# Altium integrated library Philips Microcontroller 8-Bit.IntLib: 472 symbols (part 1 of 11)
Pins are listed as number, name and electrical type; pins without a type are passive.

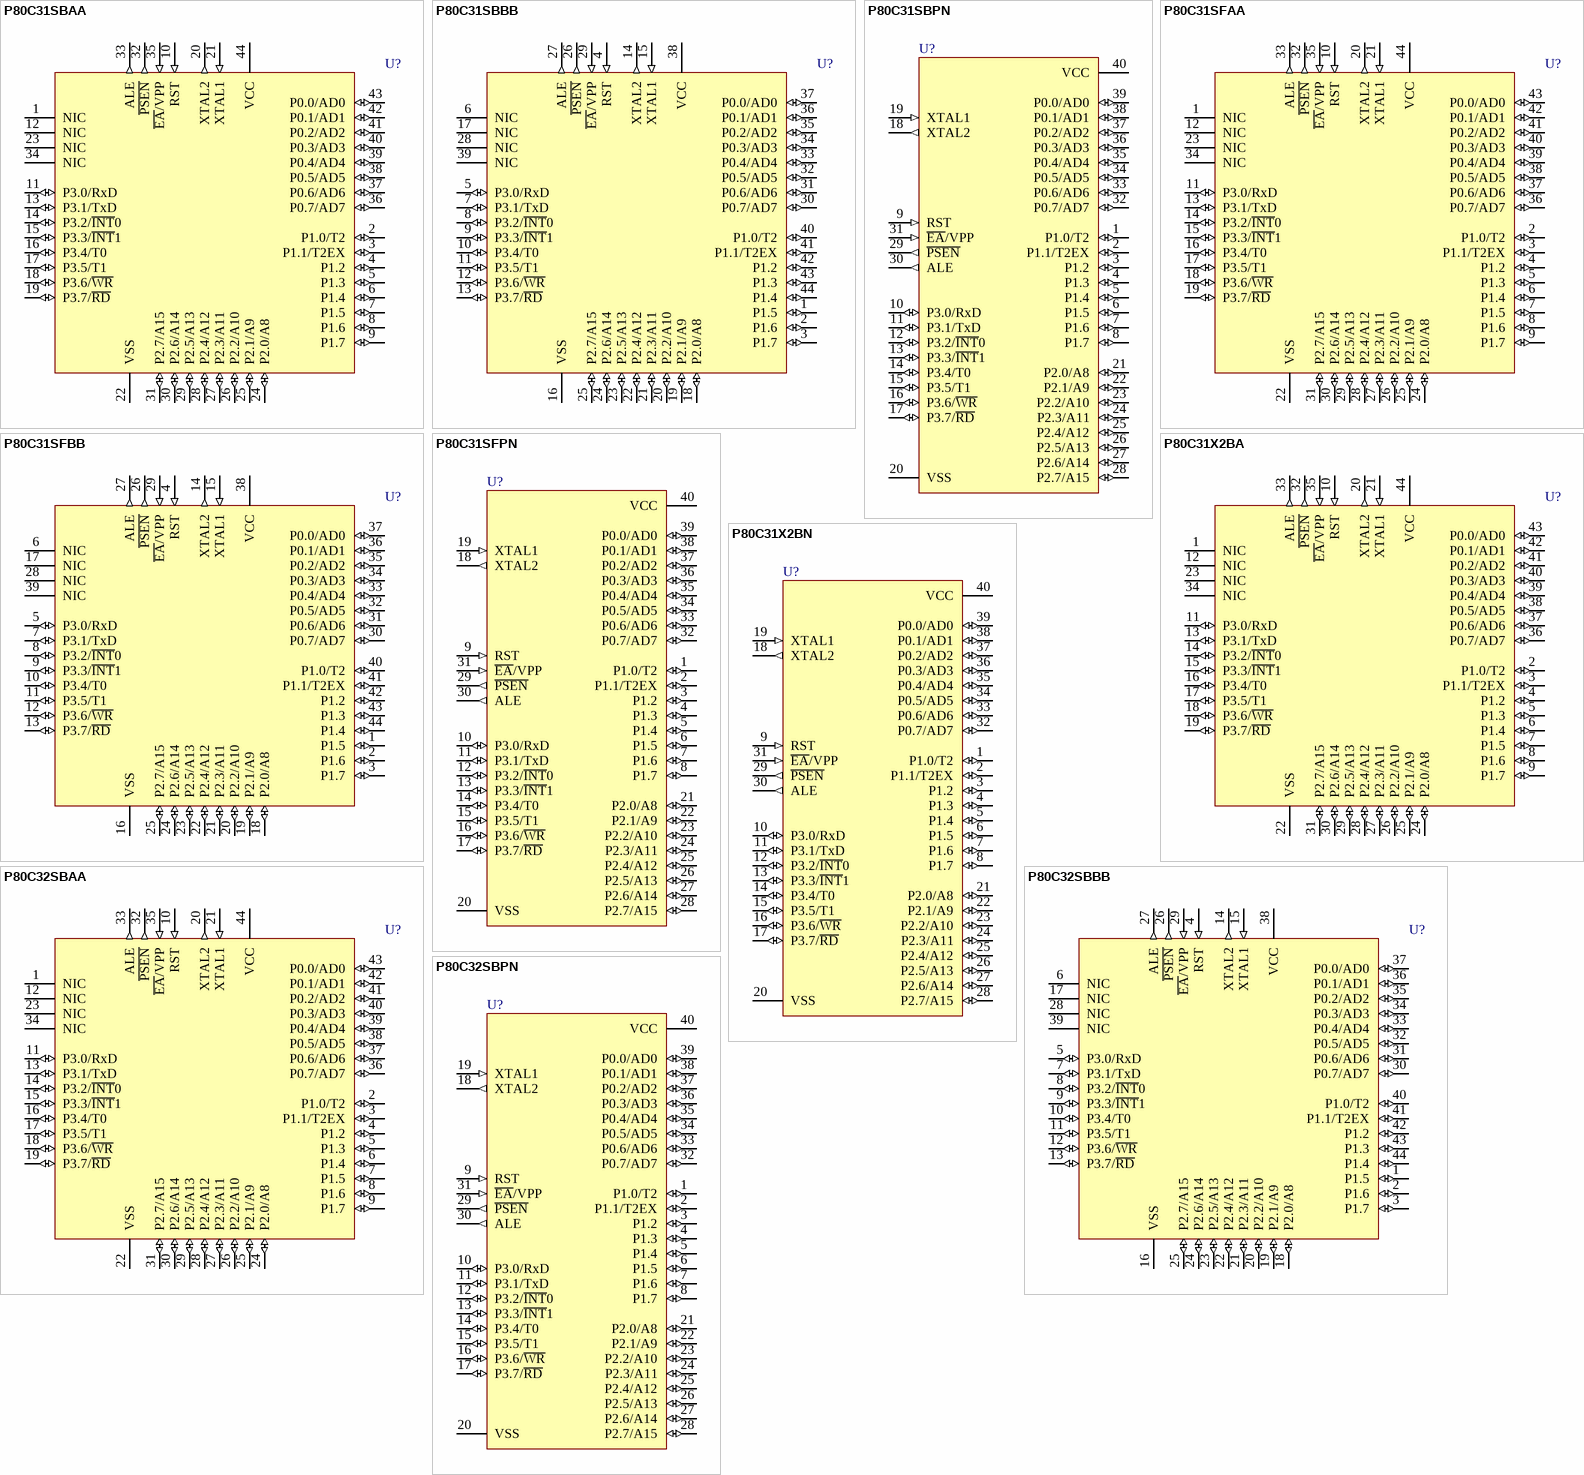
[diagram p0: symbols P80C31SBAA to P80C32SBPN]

## P80C31SBAA
designator U?
80C51 8-Bit Microcontroller Family: 128 B RAM, ROMless, 2.7 V-5.5 V, Low Power, High Speed
footprint SOT187-2_N (Leaded Chip Carrier, 44-Leads, Body 16.6x16.6mm, Pitch 1.27mm, IPC Medium Density)
footprint SOT187-2_L (Leaded Chip Carrier, 44-Leads, Body 16.6x16.6mm, Pitch 1.27mm, IPC High Density)
footprint SOT187-2_M (Leaded Chip Carrier, 44-Leads, Body 16.6x16.6mm, Pitch 1.27mm, IPC Low Density)
pins: 1 NIC, 2 P1.0/T2 (io), 3 P1.1/T2EX (io), 4 P1.2 (io), 5 P1.3 (io), 6 P1.4 (io), 7 P1.5 (io), 8 P1.6 (io), 9 P1.7 (io), 10 RST (in), 11 P3.0/RxD (io), 12 NIC, 13 P3.1/TxD (io), 14 P3.2/~{INT}0 (io), 15 P3.3/~{INT}1 (io), 16 P3.4/T0 (io), 17 P3.5/T1 (io), 18 P3.6/~{WR} (io), 19 P3.7/~{RD} (io), 20 XTAL2 (out), 21 XTAL1 (in), 22 VSS (power), 23 NIC, 24 P2.0/A8 (io), 25 P2.1/A9 (io), 26 P2.2/A10 (io), 27 P2.3/A11 (io), 28 P2.4/A12 (io), 29 P2.5/A13 (io), 30 P2.6/A14 (io), 31 P2.7/A15 (io), 32 ~{PSEN} (out), 33 ALE (out), 34 NIC, 35 ~{EA}/VPP (in), 36 P0.7/AD7 (io), 37 P0.6/AD6 (io), 38 P0.5/AD5 (io), 39 P0.4/AD4 (io), 40 P0.3/AD3 (io), 41 P0.2/AD2 (io), 42 P0.1/AD1 (io), 43 P0.0/AD0 (io), 44 VCC (power)

## P80C31SBBB
designator U?
80C51 8-Bit Microcontroller Family: 128 B RAM, ROMless, 2.7 V-5.5 V, Low Power, High Speed
footprint SOT307-2_N (QFP, 44-Leads, Body 10x10mm, Pitch 0.8mm, IPC Medium Density)
footprint SOT307-2_L (QFP, 44-Leads, Body 10x10mm, Pitch 0.8mm, IPC High Density)
footprint SOT307-2_M (QFP, 44-Leads, Body 10x10mm, Pitch 0.8mm, IPC Low Density)
pins: 1 P1.5 (io), 2 P1.6 (io), 3 P1.7 (io), 4 RST (in), 5 P3.0/RxD (io), 6 NIC, 7 P3.1/TxD (io), 8 P3.2/~{INT}0 (io), 9 P3.3/~{INT}1 (io), 10 P3.4/T0 (io), 11 P3.5/T1 (io), 12 P3.6/~{WR} (io), 13 P3.7/~{RD} (io), 14 XTAL2 (out), 15 XTAL1 (in), 16 VSS (power), 17 NIC, 18 P2.0/A8 (io), 19 P2.1/A9 (io), 20 P2.2/A10 (io), 21 P2.3/A11 (io), 22 P2.4/A12 (io), 23 P2.5/A13 (io), 24 P2.6/A14 (io), 25 P2.7/A15 (io), 26 ~{PSEN} (out), 27 ALE (out), 28 NIC, 29 ~{EA}/VPP (in), 30 P0.7/AD7 (io), 31 P0.6/AD6 (io), 32 P0.5/AD5 (io), 33 P0.4/AD4 (io), 34 P0.3/AD3 (io), 35 P0.2/AD2 (io), 36 P0.1/AD1 (io), 37 P0.0/AD0 (io), 38 VCC (power), 39 NIC, 40 P1.0/T2 (io), 41 P1.1/T2EX (io), 42 P1.2 (io), 43 P1.3 (io), 44 P1.4 (io)

## P80C31SBPN
designator U?
80C51 8-Bit Microcontroller Family: 128 B RAM, ROMless, 2.7 V-5.5 V, Low Power, High Speed
footprint SOT129-1 (DIP, Plastic; 40 Leads; Row Spacing 15.24 mm; Pitch 2.54 mm)
pins: 1 P1.0/T2 (io), 2 P1.1/T2EX (io), 3 P1.2 (io), 4 P1.3 (io), 5 P1.4 (io), 6 P1.5 (io), 7 P1.6 (io), 8 P1.7 (io), 9 RST (in), 10 P3.0/RxD (io), 11 P3.1/TxD (io), 12 P3.2/~{INT}0 (io), 13 P3.3/~{INT}1 (io), 14 P3.4/T0 (io), 15 P3.5/T1 (io), 16 P3.6/~{WR} (io), 17 P3.7/~{RD} (io), 18 XTAL2 (out), 19 XTAL1 (in), 20 VSS (power), 21 P2.0/A8 (io), 22 P2.1/A9 (io), 23 P2.2/A10 (io), 24 P2.3/A11 (io), 25 P2.4/A12 (io), 26 P2.5/A13 (io), 27 P2.6/A14 (io), 28 P2.7/A15 (io), 29 ~{PSEN} (out), 30 ALE (out), 31 ~{EA}/VPP (in), 32 P0.7/AD7 (io), 33 P0.6/AD6 (io), 34 P0.5/AD5 (io), 35 P0.4/AD4 (io), 36 P0.3/AD3 (io), 37 P0.2/AD2 (io), 38 P0.1/AD1 (io), 39 P0.0/AD0 (io), 40 VCC (power)

## P80C31SFAA
designator U?
80C51 8-Bit Microcontroller Family: 128 B RAM, ROMless, 2.7 V-5.5 V, Low Power, High Speed
footprint SOT187-2_N (Leaded Chip Carrier, 44-Leads, Body 16.6x16.6mm, Pitch 1.27mm, IPC Medium Density)
footprint SOT187-2_L (Leaded Chip Carrier, 44-Leads, Body 16.6x16.6mm, Pitch 1.27mm, IPC High Density)
footprint SOT187-2_M (Leaded Chip Carrier, 44-Leads, Body 16.6x16.6mm, Pitch 1.27mm, IPC Low Density)
pins: 1 NIC, 2 P1.0/T2 (io), 3 P1.1/T2EX (io), 4 P1.2 (io), 5 P1.3 (io), 6 P1.4 (io), 7 P1.5 (io), 8 P1.6 (io), 9 P1.7 (io), 10 RST (in), 11 P3.0/RxD (io), 12 NIC, 13 P3.1/TxD (io), 14 P3.2/~{INT}0 (io), 15 P3.3/~{INT}1 (io), 16 P3.4/T0 (io), 17 P3.5/T1 (io), 18 P3.6/~{WR} (io), 19 P3.7/~{RD} (io), 20 XTAL2 (out), 21 XTAL1 (in), 22 VSS (power), 23 NIC, 24 P2.0/A8 (io), 25 P2.1/A9 (io), 26 P2.2/A10 (io), 27 P2.3/A11 (io), 28 P2.4/A12 (io), 29 P2.5/A13 (io), 30 P2.6/A14 (io), 31 P2.7/A15 (io), 32 ~{PSEN} (out), 33 ALE (out), 34 NIC, 35 ~{EA}/VPP (in), 36 P0.7/AD7 (io), 37 P0.6/AD6 (io), 38 P0.5/AD5 (io), 39 P0.4/AD4 (io), 40 P0.3/AD3 (io), 41 P0.2/AD2 (io), 42 P0.1/AD1 (io), 43 P0.0/AD0 (io), 44 VCC (power)

## P80C31SFBB
designator U?
80C51 8-Bit Microcontroller Family: 128 B RAM, ROMless, 2.7 V-5.5 V, Low Power, High Speed
footprint SOT307-2_N (QFP, 44-Leads, Body 10x10mm, Pitch 0.8mm, IPC Medium Density)
footprint SOT307-2_L (QFP, 44-Leads, Body 10x10mm, Pitch 0.8mm, IPC High Density)
footprint SOT307-2_M (QFP, 44-Leads, Body 10x10mm, Pitch 0.8mm, IPC Low Density)
pins: 1 P1.5 (io), 2 P1.6 (io), 3 P1.7 (io), 4 RST (in), 5 P3.0/RxD (io), 6 NIC, 7 P3.1/TxD (io), 8 P3.2/~{INT}0 (io), 9 P3.3/~{INT}1 (io), 10 P3.4/T0 (io), 11 P3.5/T1 (io), 12 P3.6/~{WR} (io), 13 P3.7/~{RD} (io), 14 XTAL2 (out), 15 XTAL1 (in), 16 VSS (power), 17 NIC, 18 P2.0/A8 (io), 19 P2.1/A9 (io), 20 P2.2/A10 (io), 21 P2.3/A11 (io), 22 P2.4/A12 (io), 23 P2.5/A13 (io), 24 P2.6/A14 (io), 25 P2.7/A15 (io), 26 ~{PSEN} (out), 27 ALE (out), 28 NIC, 29 ~{EA}/VPP (in), 30 P0.7/AD7 (io), 31 P0.6/AD6 (io), 32 P0.5/AD5 (io), 33 P0.4/AD4 (io), 34 P0.3/AD3 (io), 35 P0.2/AD2 (io), 36 P0.1/AD1 (io), 37 P0.0/AD0 (io), 38 VCC (power), 39 NIC, 40 P1.0/T2 (io), 41 P1.1/T2EX (io), 42 P1.2 (io), 43 P1.3 (io), 44 P1.4 (io)

## P80C31SFPN
designator U?
80C51 8-Bit Microcontroller Family: 128 B RAM, ROMless, 2.7 V-5.5 V, Low Power, High Speed
footprint SOT129-1 (DIP, Plastic; 40 Leads; Row Spacing 15.24 mm; Pitch 2.54 mm)
pins: 1 P1.0/T2 (io), 2 P1.1/T2EX (io), 3 P1.2 (io), 4 P1.3 (io), 5 P1.4 (io), 6 P1.5 (io), 7 P1.6 (io), 8 P1.7 (io), 9 RST (in), 10 P3.0/RxD (io), 11 P3.1/TxD (io), 12 P3.2/~{INT}0 (io), 13 P3.3/~{INT}1 (io), 14 P3.4/T0 (io), 15 P3.5/T1 (io), 16 P3.6/~{WR} (io), 17 P3.7/~{RD} (io), 18 XTAL2 (out), 19 XTAL1 (in), 20 VSS (power), 21 P2.0/A8 (io), 22 P2.1/A9 (io), 23 P2.2/A10 (io), 24 P2.3/A11 (io), 25 P2.4/A12 (io), 26 P2.5/A13 (io), 27 P2.6/A14 (io), 28 P2.7/A15 (io), 29 ~{PSEN} (out), 30 ALE (out), 31 ~{EA}/VPP (in), 32 P0.7/AD7 (io), 33 P0.6/AD6 (io), 34 P0.5/AD5 (io), 35 P0.4/AD4 (io), 36 P0.3/AD3 (io), 37 P0.2/AD2 (io), 38 P0.1/AD1 (io), 39 P0.0/AD0 (io), 40 VCC (power)

## P80C31X2BA
designator U?
80C51 8-Bit Microcontroller Family: 128 B RAM, ROMless, 2.7 to 5.5 V, Low Power, High Speed
footprint SOT187-2_N (Leaded Chip Carrier, 44-Leads, Body 16.6x16.6mm, Pitch 1.27mm, IPC Medium Density)
footprint SOT187-2_L (Leaded Chip Carrier, 44-Leads, Body 16.6x16.6mm, Pitch 1.27mm, IPC High Density)
footprint SOT187-2_M (Leaded Chip Carrier, 44-Leads, Body 16.6x16.6mm, Pitch 1.27mm, IPC Low Density)
pins: 1 NIC, 2 P1.0/T2 (io), 3 P1.1/T2EX (io), 4 P1.2 (io), 5 P1.3 (io), 6 P1.4 (io), 7 P1.5 (io), 8 P1.6 (io), 9 P1.7 (io), 10 RST (in), 11 P3.0/RxD (io), 12 NIC, 13 P3.1/TxD (io), 14 P3.2/~{INT}0 (io), 15 P3.3/~{INT}1 (io), 16 P3.4/T0 (io), 17 P3.5/T1 (io), 18 P3.6/~{WR} (io), 19 P3.7/~{RD} (io), 20 XTAL2 (out), 21 XTAL1 (in), 22 VSS (power), 23 NIC, 24 P2.0/A8 (io), 25 P2.1/A9 (io), 26 P2.2/A10 (io), 27 P2.3/A11 (io), 28 P2.4/A12 (io), 29 P2.5/A13 (io), 30 P2.6/A14 (io), 31 P2.7/A15 (io), 32 ~{PSEN} (out), 33 ALE (out), 34 NIC, 35 ~{EA}/VPP (in), 36 P0.7/AD7 (io), 37 P0.6/AD6 (io), 38 P0.5/AD5 (io), 39 P0.4/AD4 (io), 40 P0.3/AD3 (io), 41 P0.2/AD2 (io), 42 P0.1/AD1 (io), 43 P0.0/AD0 (io), 44 VCC (power)

## P80C31X2BN
designator U?
80C51 8-Bit Microcontroller Family: 128 B RAM, ROMless, 2.7 to 5.5 V, Low Power, High Speed
footprint SOT129-1 (DIP, Plastic; 40 Leads; Row Spacing 15.24 mm; Pitch 2.54 mm)
pins: 1 P1.0/T2 (io), 2 P1.1/T2EX (io), 3 P1.2 (io), 4 P1.3 (io), 5 P1.4 (io), 6 P1.5 (io), 7 P1.6 (io), 8 P1.7 (io), 9 RST (in), 10 P3.0/RxD (io), 11 P3.1/TxD (io), 12 P3.2/~{INT}0 (io), 13 P3.3/~{INT}1 (io), 14 P3.4/T0 (io), 15 P3.5/T1 (io), 16 P3.6/~{WR} (io), 17 P3.7/~{RD} (io), 18 XTAL2 (out), 19 XTAL1 (in), 20 VSS (power), 21 P2.0/A8 (io), 22 P2.1/A9 (io), 23 P2.2/A10 (io), 24 P2.3/A11 (io), 25 P2.4/A12 (io), 26 P2.5/A13 (io), 27 P2.6/A14 (io), 28 P2.7/A15 (io), 29 ~{PSEN} (out), 30 ALE (out), 31 ~{EA}/VPP (in), 32 P0.7/AD7 (io), 33 P0.6/AD6 (io), 34 P0.5/AD5 (io), 35 P0.4/AD4 (io), 36 P0.3/AD3 (io), 37 P0.2/AD2 (io), 38 P0.1/AD1 (io), 39 P0.0/AD0 (io), 40 VCC (power)

## P80C32SBAA
designator U?
80C51 8-Bit Microcontroller Family: 256 B RAM, ROMless, 2.7 V-5.5 V, Low Power, High Speed
footprint SOT187-2_N (Leaded Chip Carrier, 44-Leads, Body 16.6x16.6mm, Pitch 1.27mm, IPC Medium Density)
footprint SOT187-2_L (Leaded Chip Carrier, 44-Leads, Body 16.6x16.6mm, Pitch 1.27mm, IPC High Density)
footprint SOT187-2_M (Leaded Chip Carrier, 44-Leads, Body 16.6x16.6mm, Pitch 1.27mm, IPC Low Density)
pins: 1 NIC, 2 P1.0/T2 (io), 3 P1.1/T2EX (io), 4 P1.2 (io), 5 P1.3 (io), 6 P1.4 (io), 7 P1.5 (io), 8 P1.6 (io), 9 P1.7 (io), 10 RST (in), 11 P3.0/RxD (io), 12 NIC, 13 P3.1/TxD (io), 14 P3.2/~{INT}0 (io), 15 P3.3/~{INT}1 (io), 16 P3.4/T0 (io), 17 P3.5/T1 (io), 18 P3.6/~{WR} (io), 19 P3.7/~{RD} (io), 20 XTAL2 (out), 21 XTAL1 (in), 22 VSS (power), 23 NIC, 24 P2.0/A8 (io), 25 P2.1/A9 (io), 26 P2.2/A10 (io), 27 P2.3/A11 (io), 28 P2.4/A12 (io), 29 P2.5/A13 (io), 30 P2.6/A14 (io), 31 P2.7/A15 (io), 32 ~{PSEN} (out), 33 ALE (out), 34 NIC, 35 ~{EA}/VPP (in), 36 P0.7/AD7 (io), 37 P0.6/AD6 (io), 38 P0.5/AD5 (io), 39 P0.4/AD4 (io), 40 P0.3/AD3 (io), 41 P0.2/AD2 (io), 42 P0.1/AD1 (io), 43 P0.0/AD0 (io), 44 VCC (power)

## P80C32SBBB
designator U?
80C51 8-Bit Microcontroller Family: 256 B RAM, ROMless, 2.7 V-5.5 V, Low Power, High Speed
footprint SOT307-2_N (QFP, 44-Leads, Body 10x10mm, Pitch 0.8mm, IPC Medium Density)
footprint SOT307-2_L (QFP, 44-Leads, Body 10x10mm, Pitch 0.8mm, IPC High Density)
footprint SOT307-2_M (QFP, 44-Leads, Body 10x10mm, Pitch 0.8mm, IPC Low Density)
pins: 1 P1.5 (io), 2 P1.6 (io), 3 P1.7 (io), 4 RST (in), 5 P3.0/RxD (io), 6 NIC, 7 P3.1/TxD (io), 8 P3.2/~{INT}0 (io), 9 P3.3/~{INT}1 (io), 10 P3.4/T0 (io), 11 P3.5/T1 (io), 12 P3.6/~{WR} (io), 13 P3.7/~{RD} (io), 14 XTAL2 (out), 15 XTAL1 (in), 16 VSS (power), 17 NIC, 18 P2.0/A8 (io), 19 P2.1/A9 (io), 20 P2.2/A10 (io), 21 P2.3/A11 (io), 22 P2.4/A12 (io), 23 P2.5/A13 (io), 24 P2.6/A14 (io), 25 P2.7/A15 (io), 26 ~{PSEN} (out), 27 ALE (out), 28 NIC, 29 ~{EA}/VPP (in), 30 P0.7/AD7 (io), 31 P0.6/AD6 (io), 32 P0.5/AD5 (io), 33 P0.4/AD4 (io), 34 P0.3/AD3 (io), 35 P0.2/AD2 (io), 36 P0.1/AD1 (io), 37 P0.0/AD0 (io), 38 VCC (power), 39 NIC, 40 P1.0/T2 (io), 41 P1.1/T2EX (io), 42 P1.2 (io), 43 P1.3 (io), 44 P1.4 (io)

## P80C32SBPN
designator U?
80C51 8-Bit Microcontroller Family: 256 B RAM, ROMless, 2.7 V-5.5 V, Low Power, High Speed
footprint SOT129-1 (DIP, Plastic; 40 Leads; Row Spacing 15.24 mm; Pitch 2.54 mm)
pins: 1 P1.0/T2 (io), 2 P1.1/T2EX (io), 3 P1.2 (io), 4 P1.3 (io), 5 P1.4 (io), 6 P1.5 (io), 7 P1.6 (io), 8 P1.7 (io), 9 RST (in), 10 P3.0/RxD (io), 11 P3.1/TxD (io), 12 P3.2/~{INT}0 (io), 13 P3.3/~{INT}1 (io), 14 P3.4/T0 (io), 15 P3.5/T1 (io), 16 P3.6/~{WR} (io), 17 P3.7/~{RD} (io), 18 XTAL2 (out), 19 XTAL1 (in), 20 VSS (power), 21 P2.0/A8 (io), 22 P2.1/A9 (io), 23 P2.2/A10 (io), 24 P2.3/A11 (io), 25 P2.4/A12 (io), 26 P2.5/A13 (io), 27 P2.6/A14 (io), 28 P2.7/A15 (io), 29 ~{PSEN} (out), 30 ALE (out), 31 ~{EA}/VPP (in), 32 P0.7/AD7 (io), 33 P0.6/AD6 (io), 34 P0.5/AD5 (io), 35 P0.4/AD4 (io), 36 P0.3/AD3 (io), 37 P0.2/AD2 (io), 38 P0.1/AD1 (io), 39 P0.0/AD0 (io), 40 VCC (power)

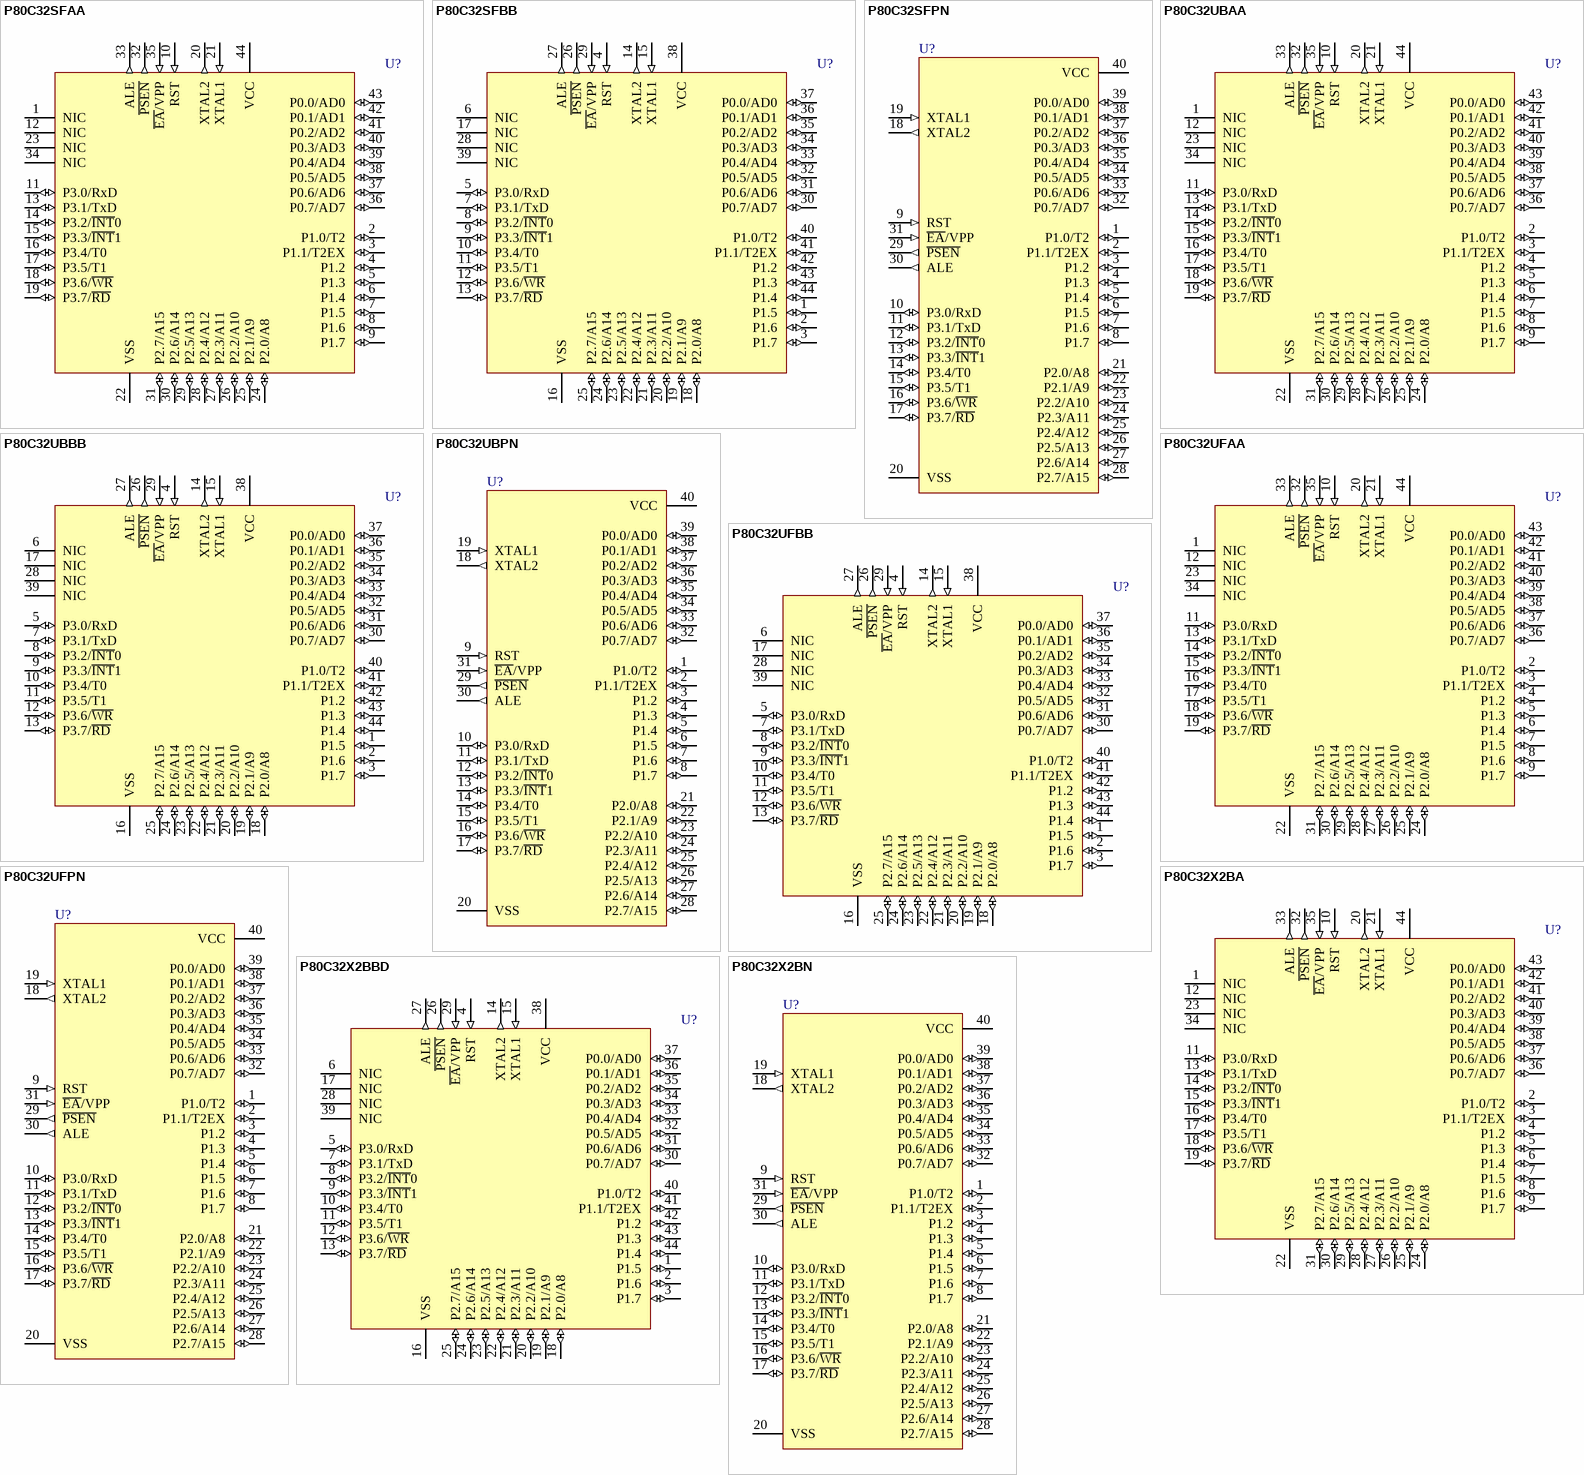
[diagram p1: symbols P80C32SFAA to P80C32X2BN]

## P80C32SFAA
designator U?
80C51 8-Bit Microcontroller Family: 256 B RAM, ROMless, 2.7 V-5.5 V, Low Power, High Speed
footprint SOT187-2_N (Leaded Chip Carrier, 44-Leads, Body 16.6x16.6mm, Pitch 1.27mm, IPC Medium Density)
footprint SOT187-2_L (Leaded Chip Carrier, 44-Leads, Body 16.6x16.6mm, Pitch 1.27mm, IPC High Density)
footprint SOT187-2_M (Leaded Chip Carrier, 44-Leads, Body 16.6x16.6mm, Pitch 1.27mm, IPC Low Density)
pins: 1 NIC, 2 P1.0/T2 (io), 3 P1.1/T2EX (io), 4 P1.2 (io), 5 P1.3 (io), 6 P1.4 (io), 7 P1.5 (io), 8 P1.6 (io), 9 P1.7 (io), 10 RST (in), 11 P3.0/RxD (io), 12 NIC, 13 P3.1/TxD (io), 14 P3.2/~{INT}0 (io), 15 P3.3/~{INT}1 (io), 16 P3.4/T0 (io), 17 P3.5/T1 (io), 18 P3.6/~{WR} (io), 19 P3.7/~{RD} (io), 20 XTAL2 (out), 21 XTAL1 (in), 22 VSS (power), 23 NIC, 24 P2.0/A8 (io), 25 P2.1/A9 (io), 26 P2.2/A10 (io), 27 P2.3/A11 (io), 28 P2.4/A12 (io), 29 P2.5/A13 (io), 30 P2.6/A14 (io), 31 P2.7/A15 (io), 32 ~{PSEN} (out), 33 ALE (out), 34 NIC, 35 ~{EA}/VPP (in), 36 P0.7/AD7 (io), 37 P0.6/AD6 (io), 38 P0.5/AD5 (io), 39 P0.4/AD4 (io), 40 P0.3/AD3 (io), 41 P0.2/AD2 (io), 42 P0.1/AD1 (io), 43 P0.0/AD0 (io), 44 VCC (power)

## P80C32SFBB
designator U?
80C51 8-Bit Microcontroller Family: 256 B RAM, ROMless, 2.7 V-5.5 V, Low Power, High Speed
footprint SOT307-2_N (QFP, 44-Leads, Body 10x10mm, Pitch 0.8mm, IPC Medium Density)
footprint SOT307-2_L (QFP, 44-Leads, Body 10x10mm, Pitch 0.8mm, IPC High Density)
footprint SOT307-2_M (QFP, 44-Leads, Body 10x10mm, Pitch 0.8mm, IPC Low Density)
pins: 1 P1.5 (io), 2 P1.6 (io), 3 P1.7 (io), 4 RST (in), 5 P3.0/RxD (io), 6 NIC, 7 P3.1/TxD (io), 8 P3.2/~{INT}0 (io), 9 P3.3/~{INT}1 (io), 10 P3.4/T0 (io), 11 P3.5/T1 (io), 12 P3.6/~{WR} (io), 13 P3.7/~{RD} (io), 14 XTAL2 (out), 15 XTAL1 (in), 16 VSS (power), 17 NIC, 18 P2.0/A8 (io), 19 P2.1/A9 (io), 20 P2.2/A10 (io), 21 P2.3/A11 (io), 22 P2.4/A12 (io), 23 P2.5/A13 (io), 24 P2.6/A14 (io), 25 P2.7/A15 (io), 26 ~{PSEN} (out), 27 ALE (out), 28 NIC, 29 ~{EA}/VPP (in), 30 P0.7/AD7 (io), 31 P0.6/AD6 (io), 32 P0.5/AD5 (io), 33 P0.4/AD4 (io), 34 P0.3/AD3 (io), 35 P0.2/AD2 (io), 36 P0.1/AD1 (io), 37 P0.0/AD0 (io), 38 VCC (power), 39 NIC, 40 P1.0/T2 (io), 41 P1.1/T2EX (io), 42 P1.2 (io), 43 P1.3 (io), 44 P1.4 (io)

## P80C32SFPN
designator U?
80C51 8-Bit Microcontroller Family: 256 B RAM, ROMless, 2.7 V-5.5 V, Low Power, High Speed
footprint SOT129-1 (DIP, Plastic; 40 Leads; Row Spacing 15.24 mm; Pitch 2.54 mm)
pins: 1 P1.0/T2 (io), 2 P1.1/T2EX (io), 3 P1.2 (io), 4 P1.3 (io), 5 P1.4 (io), 6 P1.5 (io), 7 P1.6 (io), 8 P1.7 (io), 9 RST (in), 10 P3.0/RxD (io), 11 P3.1/TxD (io), 12 P3.2/~{INT}0 (io), 13 P3.3/~{INT}1 (io), 14 P3.4/T0 (io), 15 P3.5/T1 (io), 16 P3.6/~{WR} (io), 17 P3.7/~{RD} (io), 18 XTAL2 (out), 19 XTAL1 (in), 20 VSS (power), 21 P2.0/A8 (io), 22 P2.1/A9 (io), 23 P2.2/A10 (io), 24 P2.3/A11 (io), 25 P2.4/A12 (io), 26 P2.5/A13 (io), 27 P2.6/A14 (io), 28 P2.7/A15 (io), 29 ~{PSEN} (out), 30 ALE (out), 31 ~{EA}/VPP (in), 32 P0.7/AD7 (io), 33 P0.6/AD6 (io), 34 P0.5/AD5 (io), 35 P0.4/AD4 (io), 36 P0.3/AD3 (io), 37 P0.2/AD2 (io), 38 P0.1/AD1 (io), 39 P0.0/AD0 (io), 40 VCC (power)

## P80C32UBAA
designator U?
80C51 8-Bit Microcontroller Family: 256 B RAM, ROMless, 2.7 V-5.5 V, Low Power, High Speed
footprint SOT187-2_N (Leaded Chip Carrier, 44-Leads, Body 16.6x16.6mm, Pitch 1.27mm, IPC Medium Density)
footprint SOT187-2_L (Leaded Chip Carrier, 44-Leads, Body 16.6x16.6mm, Pitch 1.27mm, IPC High Density)
footprint SOT187-2_M (Leaded Chip Carrier, 44-Leads, Body 16.6x16.6mm, Pitch 1.27mm, IPC Low Density)
pins: 1 NIC, 2 P1.0/T2 (io), 3 P1.1/T2EX (io), 4 P1.2 (io), 5 P1.3 (io), 6 P1.4 (io), 7 P1.5 (io), 8 P1.6 (io), 9 P1.7 (io), 10 RST (in), 11 P3.0/RxD (io), 12 NIC, 13 P3.1/TxD (io), 14 P3.2/~{INT}0 (io), 15 P3.3/~{INT}1 (io), 16 P3.4/T0 (io), 17 P3.5/T1 (io), 18 P3.6/~{WR} (io), 19 P3.7/~{RD} (io), 20 XTAL2 (out), 21 XTAL1 (in), 22 VSS (power), 23 NIC, 24 P2.0/A8 (io), 25 P2.1/A9 (io), 26 P2.2/A10 (io), 27 P2.3/A11 (io), 28 P2.4/A12 (io), 29 P2.5/A13 (io), 30 P2.6/A14 (io), 31 P2.7/A15 (io), 32 ~{PSEN} (out), 33 ALE (out), 34 NIC, 35 ~{EA}/VPP (in), 36 P0.7/AD7 (io), 37 P0.6/AD6 (io), 38 P0.5/AD5 (io), 39 P0.4/AD4 (io), 40 P0.3/AD3 (io), 41 P0.2/AD2 (io), 42 P0.1/AD1 (io), 43 P0.0/AD0 (io), 44 VCC (power)

## P80C32UBBB
designator U?
80C51 8-Bit Microcontroller Family: 256 B RAM, ROMless, 2.7 V-5.5 V, Low Power, High Speed
footprint SOT307-2_N (QFP, 44-Leads, Body 10x10mm, Pitch 0.8mm, IPC Medium Density)
footprint SOT307-2_L (QFP, 44-Leads, Body 10x10mm, Pitch 0.8mm, IPC High Density)
footprint SOT307-2_M (QFP, 44-Leads, Body 10x10mm, Pitch 0.8mm, IPC Low Density)
pins: 1 P1.5 (io), 2 P1.6 (io), 3 P1.7 (io), 4 RST (in), 5 P3.0/RxD (io), 6 NIC, 7 P3.1/TxD (io), 8 P3.2/~{INT}0 (io), 9 P3.3/~{INT}1 (io), 10 P3.4/T0 (io), 11 P3.5/T1 (io), 12 P3.6/~{WR} (io), 13 P3.7/~{RD} (io), 14 XTAL2 (out), 15 XTAL1 (in), 16 VSS (power), 17 NIC, 18 P2.0/A8 (io), 19 P2.1/A9 (io), 20 P2.2/A10 (io), 21 P2.3/A11 (io), 22 P2.4/A12 (io), 23 P2.5/A13 (io), 24 P2.6/A14 (io), 25 P2.7/A15 (io), 26 ~{PSEN} (out), 27 ALE (out), 28 NIC, 29 ~{EA}/VPP (in), 30 P0.7/AD7 (io), 31 P0.6/AD6 (io), 32 P0.5/AD5 (io), 33 P0.4/AD4 (io), 34 P0.3/AD3 (io), 35 P0.2/AD2 (io), 36 P0.1/AD1 (io), 37 P0.0/AD0 (io), 38 VCC (power), 39 NIC, 40 P1.0/T2 (io), 41 P1.1/T2EX (io), 42 P1.2 (io), 43 P1.3 (io), 44 P1.4 (io)

## P80C32UBPN
designator U?
80C51 8-Bit Microcontroller Family: 256 B RAM, ROMless, 2.7 V-5.5 V, Low Power, High Speed
footprint SOT129-1 (DIP, Plastic; 40 Leads; Row Spacing 15.24 mm; Pitch 2.54 mm)
pins: 1 P1.0/T2 (io), 2 P1.1/T2EX (io), 3 P1.2 (io), 4 P1.3 (io), 5 P1.4 (io), 6 P1.5 (io), 7 P1.6 (io), 8 P1.7 (io), 9 RST (in), 10 P3.0/RxD (io), 11 P3.1/TxD (io), 12 P3.2/~{INT}0 (io), 13 P3.3/~{INT}1 (io), 14 P3.4/T0 (io), 15 P3.5/T1 (io), 16 P3.6/~{WR} (io), 17 P3.7/~{RD} (io), 18 XTAL2 (out), 19 XTAL1 (in), 20 VSS (power), 21 P2.0/A8 (io), 22 P2.1/A9 (io), 23 P2.2/A10 (io), 24 P2.3/A11 (io), 25 P2.4/A12 (io), 26 P2.5/A13 (io), 27 P2.6/A14 (io), 28 P2.7/A15 (io), 29 ~{PSEN} (out), 30 ALE (out), 31 ~{EA}/VPP (in), 32 P0.7/AD7 (io), 33 P0.6/AD6 (io), 34 P0.5/AD5 (io), 35 P0.4/AD4 (io), 36 P0.3/AD3 (io), 37 P0.2/AD2 (io), 38 P0.1/AD1 (io), 39 P0.0/AD0 (io), 40 VCC (power)

## P80C32UFAA
designator U?
80C51 8-Bit Microcontroller Family: 256 B RAM, ROMless, 2.7 V-5.5 V, Low Power, High Speed
footprint SOT187-2_N (Leaded Chip Carrier, 44-Leads, Body 16.6x16.6mm, Pitch 1.27mm, IPC Medium Density)
footprint SOT187-2_L (Leaded Chip Carrier, 44-Leads, Body 16.6x16.6mm, Pitch 1.27mm, IPC High Density)
footprint SOT187-2_M (Leaded Chip Carrier, 44-Leads, Body 16.6x16.6mm, Pitch 1.27mm, IPC Low Density)
pins: 1 NIC, 2 P1.0/T2 (io), 3 P1.1/T2EX (io), 4 P1.2 (io), 5 P1.3 (io), 6 P1.4 (io), 7 P1.5 (io), 8 P1.6 (io), 9 P1.7 (io), 10 RST (in), 11 P3.0/RxD (io), 12 NIC, 13 P3.1/TxD (io), 14 P3.2/~{INT}0 (io), 15 P3.3/~{INT}1 (io), 16 P3.4/T0 (io), 17 P3.5/T1 (io), 18 P3.6/~{WR} (io), 19 P3.7/~{RD} (io), 20 XTAL2 (out), 21 XTAL1 (in), 22 VSS (power), 23 NIC, 24 P2.0/A8 (io), 25 P2.1/A9 (io), 26 P2.2/A10 (io), 27 P2.3/A11 (io), 28 P2.4/A12 (io), 29 P2.5/A13 (io), 30 P2.6/A14 (io), 31 P2.7/A15 (io), 32 ~{PSEN} (out), 33 ALE (out), 34 NIC, 35 ~{EA}/VPP (in), 36 P0.7/AD7 (io), 37 P0.6/AD6 (io), 38 P0.5/AD5 (io), 39 P0.4/AD4 (io), 40 P0.3/AD3 (io), 41 P0.2/AD2 (io), 42 P0.1/AD1 (io), 43 P0.0/AD0 (io), 44 VCC (power)

## P80C32UFBB
designator U?
80C51 8-Bit Microcontroller Family: 256 B RAM, ROMless, 2.7 V-5.5 V, Low Power, High Speed
footprint SOT307-2_N (QFP, 44-Leads, Body 10x10mm, Pitch 0.8mm, IPC Medium Density)
footprint SOT307-2_L (QFP, 44-Leads, Body 10x10mm, Pitch 0.8mm, IPC High Density)
footprint SOT307-2_M (QFP, 44-Leads, Body 10x10mm, Pitch 0.8mm, IPC Low Density)
pins: 1 P1.5 (io), 2 P1.6 (io), 3 P1.7 (io), 4 RST (in), 5 P3.0/RxD (io), 6 NIC, 7 P3.1/TxD (io), 8 P3.2/~{INT}0 (io), 9 P3.3/~{INT}1 (io), 10 P3.4/T0 (io), 11 P3.5/T1 (io), 12 P3.6/~{WR} (io), 13 P3.7/~{RD} (io), 14 XTAL2 (out), 15 XTAL1 (in), 16 VSS (power), 17 NIC, 18 P2.0/A8 (io), 19 P2.1/A9 (io), 20 P2.2/A10 (io), 21 P2.3/A11 (io), 22 P2.4/A12 (io), 23 P2.5/A13 (io), 24 P2.6/A14 (io), 25 P2.7/A15 (io), 26 ~{PSEN} (out), 27 ALE (out), 28 NIC, 29 ~{EA}/VPP (in), 30 P0.7/AD7 (io), 31 P0.6/AD6 (io), 32 P0.5/AD5 (io), 33 P0.4/AD4 (io), 34 P0.3/AD3 (io), 35 P0.2/AD2 (io), 36 P0.1/AD1 (io), 37 P0.0/AD0 (io), 38 VCC (power), 39 NIC, 40 P1.0/T2 (io), 41 P1.1/T2EX (io), 42 P1.2 (io), 43 P1.3 (io), 44 P1.4 (io)

## P80C32UFPN
designator U?
80C51 8-Bit Microcontroller Family: 256 B RAM, ROMless, 2.7 V-5.5 V, Low Power, High Speed
footprint SOT129-1 (DIP, Plastic; 40 Leads; Row Spacing 15.24 mm; Pitch 2.54 mm)
pins: 1 P1.0/T2 (io), 2 P1.1/T2EX (io), 3 P1.2 (io), 4 P1.3 (io), 5 P1.4 (io), 6 P1.5 (io), 7 P1.6 (io), 8 P1.7 (io), 9 RST (in), 10 P3.0/RxD (io), 11 P3.1/TxD (io), 12 P3.2/~{INT}0 (io), 13 P3.3/~{INT}1 (io), 14 P3.4/T0 (io), 15 P3.5/T1 (io), 16 P3.6/~{WR} (io), 17 P3.7/~{RD} (io), 18 XTAL2 (out), 19 XTAL1 (in), 20 VSS (power), 21 P2.0/A8 (io), 22 P2.1/A9 (io), 23 P2.2/A10 (io), 24 P2.3/A11 (io), 25 P2.4/A12 (io), 26 P2.5/A13 (io), 27 P2.6/A14 (io), 28 P2.7/A15 (io), 29 ~{PSEN} (out), 30 ALE (out), 31 ~{EA}/VPP (in), 32 P0.7/AD7 (io), 33 P0.6/AD6 (io), 34 P0.5/AD5 (io), 35 P0.4/AD4 (io), 36 P0.3/AD3 (io), 37 P0.2/AD2 (io), 38 P0.1/AD1 (io), 39 P0.0/AD0 (io), 40 VCC (power)

## P80C32X2BA
designator U?
80C51 8-Bit Microcontroller Family: 256 B RAM, ROMless, 2.7 to 5.5 V, Low Power, High Speed
footprint SOT187-2_N (Leaded Chip Carrier, 44-Leads, Body 16.6x16.6mm, Pitch 1.27mm, IPC Medium Density)
footprint SOT187-2_L (Leaded Chip Carrier, 44-Leads, Body 16.6x16.6mm, Pitch 1.27mm, IPC High Density)
footprint SOT187-2_M (Leaded Chip Carrier, 44-Leads, Body 16.6x16.6mm, Pitch 1.27mm, IPC Low Density)
pins: 1 NIC, 2 P1.0/T2 (io), 3 P1.1/T2EX (io), 4 P1.2 (io), 5 P1.3 (io), 6 P1.4 (io), 7 P1.5 (io), 8 P1.6 (io), 9 P1.7 (io), 10 RST (in), 11 P3.0/RxD (io), 12 NIC, 13 P3.1/TxD (io), 14 P3.2/~{INT}0 (io), 15 P3.3/~{INT}1 (io), 16 P3.4/T0 (io), 17 P3.5/T1 (io), 18 P3.6/~{WR} (io), 19 P3.7/~{RD} (io), 20 XTAL2 (out), 21 XTAL1 (in), 22 VSS (power), 23 NIC, 24 P2.0/A8 (io), 25 P2.1/A9 (io), 26 P2.2/A10 (io), 27 P2.3/A11 (io), 28 P2.4/A12 (io), 29 P2.5/A13 (io), 30 P2.6/A14 (io), 31 P2.7/A15 (io), 32 ~{PSEN} (out), 33 ALE (out), 34 NIC, 35 ~{EA}/VPP (in), 36 P0.7/AD7 (io), 37 P0.6/AD6 (io), 38 P0.5/AD5 (io), 39 P0.4/AD4 (io), 40 P0.3/AD3 (io), 41 P0.2/AD2 (io), 42 P0.1/AD1 (io), 43 P0.0/AD0 (io), 44 VCC (power)

## P80C32X2BBD
designator U?
80C51 8-Bit Microcontroller Family: 256 B RAM, ROMless, 2.7 to 5.5 V, Low Power, High Speed
footprint SOT389-1_N (Thin QFP, 44-Leads, Body 10x10mm, Pitch 0.8mm, IPC Medium Density)
footprint SOT389-1_L (Thin QFP, 44-Leads, Body 10x10mm, Pitch 0.8mm, IPC High Density)
footprint SOT389-1_M (Thin QFP, 44-Leads, Body 10x10mm, Pitch 0.8mm, IPC Low Density)
pins: 1 P1.5 (io), 2 P1.6 (io), 3 P1.7 (io), 4 RST (in), 5 P3.0/RxD (io), 6 NIC, 7 P3.1/TxD (io), 8 P3.2/~{INT}0 (io), 9 P3.3/~{INT}1 (io), 10 P3.4/T0 (io), 11 P3.5/T1 (io), 12 P3.6/~{WR} (io), 13 P3.7/~{RD} (io), 14 XTAL2 (out), 15 XTAL1 (in), 16 VSS (power), 17 NIC, 18 P2.0/A8 (io), 19 P2.1/A9 (io), 20 P2.2/A10 (io), 21 P2.3/A11 (io), 22 P2.4/A12 (io), 23 P2.5/A13 (io), 24 P2.6/A14 (io), 25 P2.7/A15 (io), 26 ~{PSEN} (out), 27 ALE (out), 28 NIC, 29 ~{EA}/VPP (in), 30 P0.7/AD7 (io), 31 P0.6/AD6 (io), 32 P0.5/AD5 (io), 33 P0.4/AD4 (io), 34 P0.3/AD3 (io), 35 P0.2/AD2 (io), 36 P0.1/AD1 (io), 37 P0.0/AD0 (io), 38 VCC (power), 39 NIC, 40 P1.0/T2 (io), 41 P1.1/T2EX (io), 42 P1.2 (io), 43 P1.3 (io), 44 P1.4 (io)

## P80C32X2BN
designator U?
80C51 8-Bit Microcontroller Family: 256 B RAM, ROMless, 2.7 to 5.5 V, Low Power, High Speed
footprint SOT129-1 (DIP, Plastic; 40 Leads; Row Spacing 15.24 mm; Pitch 2.54 mm)
pins: 1 P1.0/T2 (io), 2 P1.1/T2EX (io), 3 P1.2 (io), 4 P1.3 (io), 5 P1.4 (io), 6 P1.5 (io), 7 P1.6 (io), 8 P1.7 (io), 9 RST (in), 10 P3.0/RxD (io), 11 P3.1/TxD (io), 12 P3.2/~{INT}0 (io), 13 P3.3/~{INT}1 (io), 14 P3.4/T0 (io), 15 P3.5/T1 (io), 16 P3.6/~{WR} (io), 17 P3.7/~{RD} (io), 18 XTAL2 (out), 19 XTAL1 (in), 20 VSS (power), 21 P2.0/A8 (io), 22 P2.1/A9 (io), 23 P2.2/A10 (io), 24 P2.3/A11 (io), 25 P2.4/A12 (io), 26 P2.5/A13 (io), 27 P2.6/A14 (io), 28 P2.7/A15 (io), 29 ~{PSEN} (out), 30 ALE (out), 31 ~{EA}/VPP (in), 32 P0.7/AD7 (io), 33 P0.6/AD6 (io), 34 P0.5/AD5 (io), 35 P0.4/AD4 (io), 36 P0.3/AD3 (io), 37 P0.2/AD2 (io), 38 P0.1/AD1 (io), 39 P0.0/AD0 (io), 40 VCC (power)

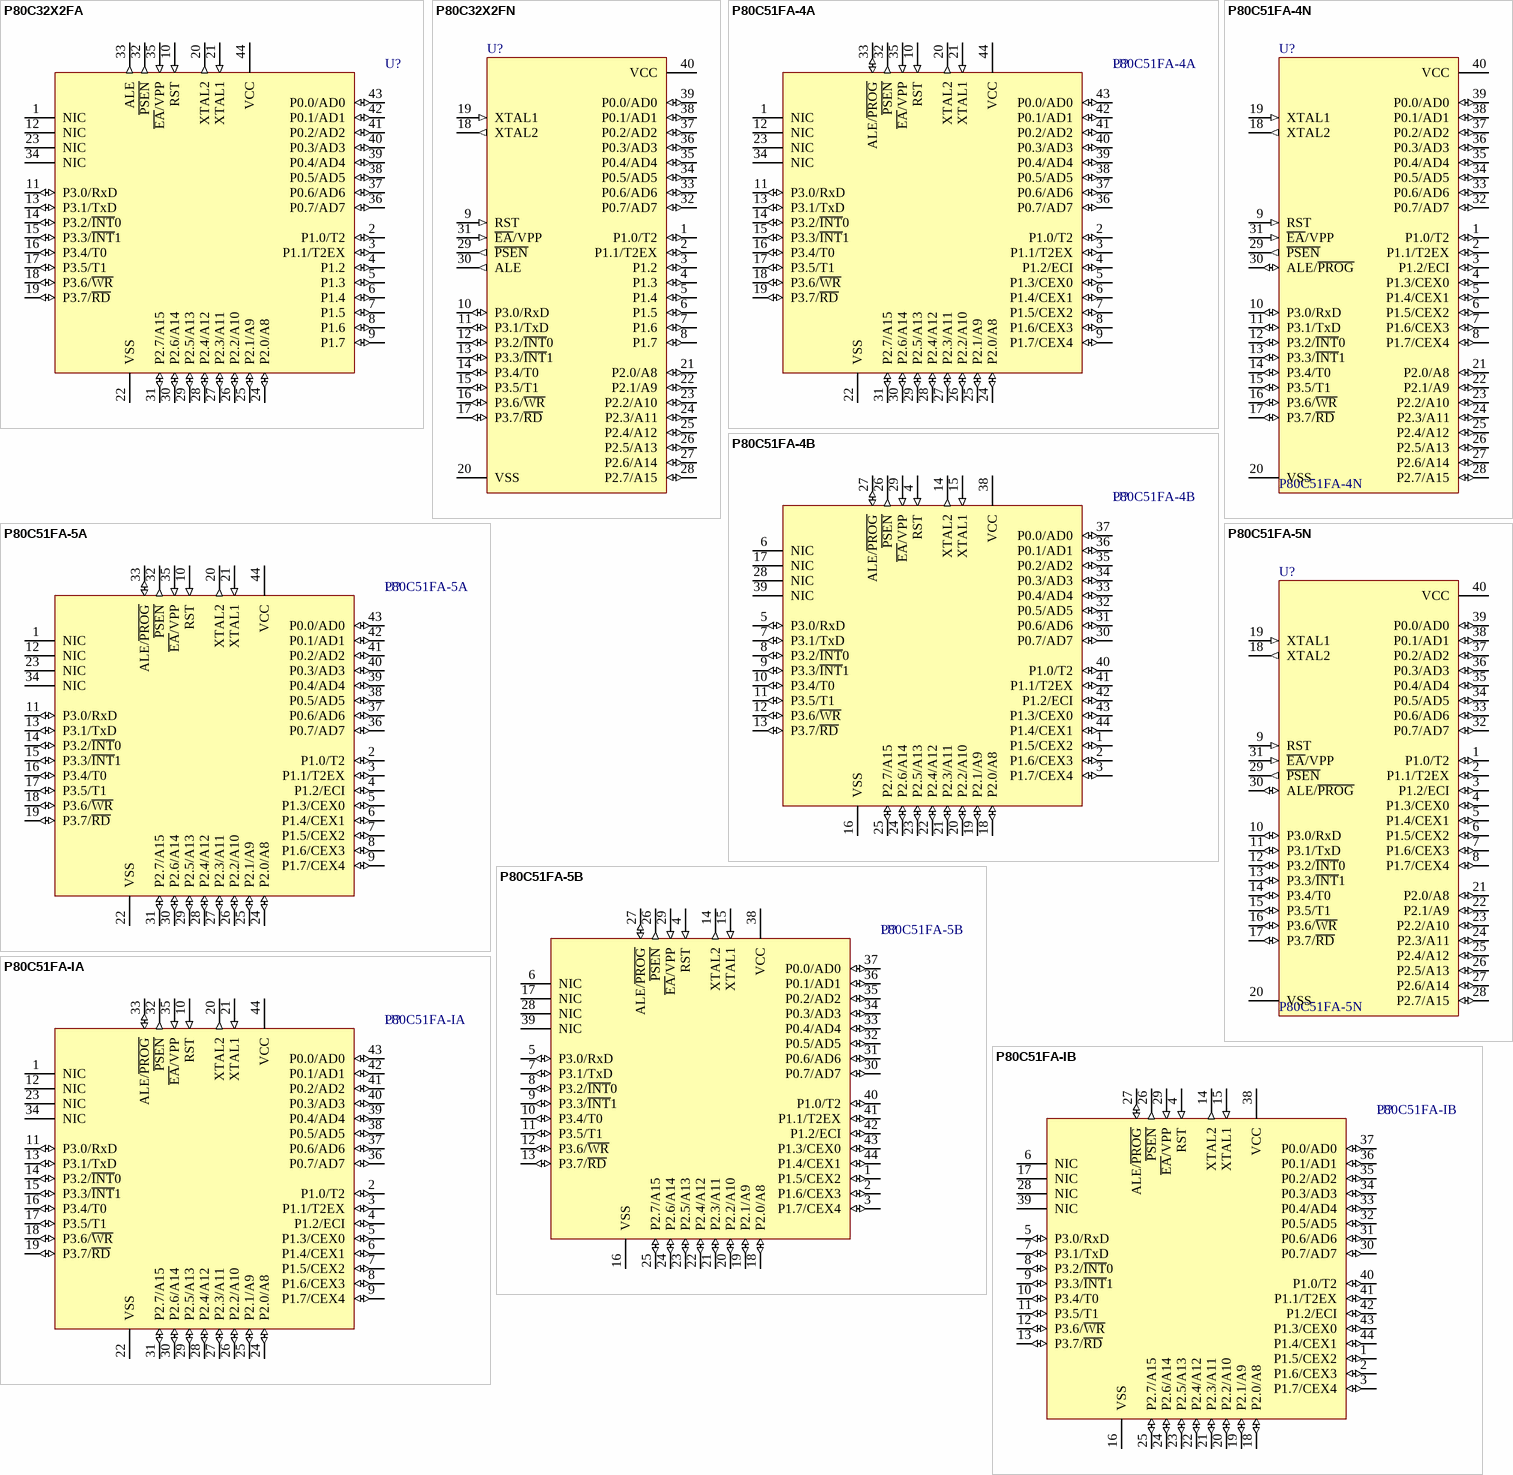
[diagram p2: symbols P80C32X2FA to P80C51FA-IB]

## P80C32X2FA
designator U?
80C51 8-Bit Microcontroller Family: 256 B RAM, ROMless, 2.7 to 5.5 V, Low Power, High Speed
footprint SOT187-2_N (Leaded Chip Carrier, 44-Leads, Body 16.6x16.6mm, Pitch 1.27mm, IPC Medium Density)
footprint SOT187-2_L (Leaded Chip Carrier, 44-Leads, Body 16.6x16.6mm, Pitch 1.27mm, IPC High Density)
footprint SOT187-2_M (Leaded Chip Carrier, 44-Leads, Body 16.6x16.6mm, Pitch 1.27mm, IPC Low Density)
pins: 1 NIC, 2 P1.0/T2 (io), 3 P1.1/T2EX (io), 4 P1.2 (io), 5 P1.3 (io), 6 P1.4 (io), 7 P1.5 (io), 8 P1.6 (io), 9 P1.7 (io), 10 RST (in), 11 P3.0/RxD (io), 12 NIC, 13 P3.1/TxD (io), 14 P3.2/~{INT}0 (io), 15 P3.3/~{INT}1 (io), 16 P3.4/T0 (io), 17 P3.5/T1 (io), 18 P3.6/~{WR} (io), 19 P3.7/~{RD} (io), 20 XTAL2 (out), 21 XTAL1 (in), 22 VSS (power), 23 NIC, 24 P2.0/A8 (io), 25 P2.1/A9 (io), 26 P2.2/A10 (io), 27 P2.3/A11 (io), 28 P2.4/A12 (io), 29 P2.5/A13 (io), 30 P2.6/A14 (io), 31 P2.7/A15 (io), 32 ~{PSEN} (out), 33 ALE (out), 34 NIC, 35 ~{EA}/VPP (in), 36 P0.7/AD7 (io), 37 P0.6/AD6 (io), 38 P0.5/AD5 (io), 39 P0.4/AD4 (io), 40 P0.3/AD3 (io), 41 P0.2/AD2 (io), 42 P0.1/AD1 (io), 43 P0.0/AD0 (io), 44 VCC (power)

## P80C32X2FN
designator U?
80C51 8-Bit Microcontroller Family: 256 B RAM, ROMless, 2.7 to 5.5 V, Low Power, High Speed
footprint SOT129-1 (DIP, Plastic; 40 Leads; Row Spacing 15.24 mm; Pitch 2.54 mm)
pins: 1 P1.0/T2 (io), 2 P1.1/T2EX (io), 3 P1.2 (io), 4 P1.3 (io), 5 P1.4 (io), 6 P1.5 (io), 7 P1.6 (io), 8 P1.7 (io), 9 RST (in), 10 P3.0/RxD (io), 11 P3.1/TxD (io), 12 P3.2/~{INT}0 (io), 13 P3.3/~{INT}1 (io), 14 P3.4/T0 (io), 15 P3.5/T1 (io), 16 P3.6/~{WR} (io), 17 P3.7/~{RD} (io), 18 XTAL2 (out), 19 XTAL1 (in), 20 VSS (power), 21 P2.0/A8 (io), 22 P2.1/A9 (io), 23 P2.2/A10 (io), 24 P2.3/A11 (io), 25 P2.4/A12 (io), 26 P2.5/A13 (io), 27 P2.6/A14 (io), 28 P2.7/A15 (io), 29 ~{PSEN} (out), 30 ALE (out), 31 ~{EA}/VPP (in), 32 P0.7/AD7 (io), 33 P0.6/AD6 (io), 34 P0.5/AD5 (io), 35 P0.4/AD4 (io), 36 P0.3/AD3 (io), 37 P0.2/AD2 (io), 38 P0.1/AD1 (io), 39 P0.0/AD0 (io), 40 VCC (power)

## P80C51FA-4A
designator U?
80C51 8-Bit Microcontroller Family: 128 B RAM, ROMless, 2.7V-5.5V, Low Power, High Speed
footprint SOT187-2_N (Leaded Chip Carrier, 44-Leads, Body 16.6x16.6mm, Pitch 1.27mm, IPC Medium Density)
footprint SOT187-2_L (Leaded Chip Carrier, 44-Leads, Body 16.6x16.6mm, Pitch 1.27mm, IPC High Density)
footprint SOT187-2_M (Leaded Chip Carrier, 44-Leads, Body 16.6x16.6mm, Pitch 1.27mm, IPC Low Density)
pins: 1 NIC, 2 P1.0/T2 (io), 3 P1.1/T2EX (io), 4 P1.2/ECI (io), 5 P1.3/CEX0 (io), 6 P1.4/CEX1 (io), 7 P1.5/CEX2 (io), 8 P1.6/CEX3 (io), 9 P1.7/CEX4 (io), 10 RST (in), 11 P3.0/RxD (io), 12 NIC, 13 P3.1/TxD (io), 14 P3.2/~{INT}0 (io), 15 P3.3/~{INT}1 (io), 16 P3.4/T0 (io), 17 P3.5/T1 (io), 18 P3.6/~{WR} (io), 19 P3.7/~{RD} (io), 20 XTAL2 (out), 21 XTAL1 (in), 22 VSS (power), 23 NIC, 24 P2.0/A8 (io), 25 P2.1/A9 (io), 26 P2.2/A10 (io), 27 P2.3/A11 (io), 28 P2.4/A12 (io), 29 P2.5/A13 (io), 30 P2.6/A14 (io), 31 P2.7/A15 (io), 32 ~{PSEN} (out), 33 ALE/~{PROG} (io), 34 NIC, 35 ~{EA}/VPP (in), 36 P0.7/AD7 (io), 37 P0.6/AD6 (io), 38 P0.5/AD5 (io), 39 P0.4/AD4 (io), 40 P0.3/AD3 (io), 41 P0.2/AD2 (io), 42 P0.1/AD1 (io), 43 P0.0/AD0 (io), 44 VCC (power)

## P80C51FA-4B
designator U?
80C51 8-Bit Microcontroller Family: 128 B RAM, ROMless, 2.7V-5.5V, Low Power, High Speed
footprint SOT307-2_N (QFP, 44-Leads, Body 10x10mm, Pitch 0.8mm, IPC Medium Density)
footprint SOT307-2_L (QFP, 44-Leads, Body 10x10mm, Pitch 0.8mm, IPC High Density)
footprint SOT307-2_M (QFP, 44-Leads, Body 10x10mm, Pitch 0.8mm, IPC Low Density)
pins: 1 P1.5/CEX2 (io), 2 P1.6/CEX3 (io), 3 P1.7/CEX4 (io), 4 RST (in), 5 P3.0/RxD (io), 6 NIC, 7 P3.1/TxD (io), 8 P3.2/~{INT}0 (io), 9 P3.3/~{INT}1 (io), 10 P3.4/T0 (io), 11 P3.5/T1 (io), 12 P3.6/~{WR} (io), 13 P3.7/~{RD} (io), 14 XTAL2 (out), 15 XTAL1 (in), 16 VSS (power), 17 NIC, 18 P2.0/A8 (io), 19 P2.1/A9 (io), 20 P2.2/A10 (io), 21 P2.3/A11 (io), 22 P2.4/A12 (io), 23 P2.5/A13 (io), 24 P2.6/A14 (io), 25 P2.7/A15 (io), 26 ~{PSEN} (out), 27 ALE/~{PROG} (io), 28 NIC, 29 ~{EA}/VPP (in), 30 P0.7/AD7 (io), 31 P0.6/AD6 (io), 32 P0.5/AD5 (io), 33 P0.4/AD4 (io), 34 P0.3/AD3 (io), 35 P0.2/AD2 (io), 36 P0.1/AD1 (io), 37 P0.0/AD0 (io), 38 VCC (power), 39 NIC, 40 P1.0/T2 (io), 41 P1.1/T2EX (io), 42 P1.2/ECI (io), 43 P1.3/CEX0 (io), 44 P1.4/CEX1 (io)

## P80C51FA-4N
designator U?
80C51 8-Bit Microcontroller Family: 128 B RAM, ROMless, 2.7V-5.5V, Low Power, High Speed
footprint SOT129-1 (DIP, Plastic; 40 Leads; Row Spacing 15.24 mm; Pitch 2.54 mm)
pins: 1 P1.0/T2 (io), 2 P1.1/T2EX (io), 3 P1.2/ECI (io), 4 P1.3/CEX0 (io), 5 P1.4/CEX1 (io), 6 P1.5/CEX2 (io), 7 P1.6/CEX3 (io), 8 P1.7/CEX4 (io), 9 RST (in), 10 P3.0/RxD (io), 11 P3.1/TxD (io), 12 P3.2/~{INT}0 (io), 13 P3.3/~{INT}1 (io), 14 P3.4/T0 (io), 15 P3.5/T1 (io), 16 P3.6/~{WR} (io), 17 P3.7/~{RD} (io), 18 XTAL2 (out), 19 XTAL1 (in), 20 VSS (power), 21 P2.0/A8 (io), 22 P2.1/A9 (io), 23 P2.2/A10 (io), 24 P2.3/A11 (io), 25 P2.4/A12 (io), 26 P2.5/A13 (io), 27 P2.6/A14 (io), 28 P2.7/A15 (io), 29 ~{PSEN} (out), 30 ALE/~{PROG} (io), 31 ~{EA}/VPP (in), 32 P0.7/AD7 (io), 33 P0.6/AD6 (io), 34 P0.5/AD5 (io), 35 P0.4/AD4 (io), 36 P0.3/AD3 (io), 37 P0.2/AD2 (io), 38 P0.1/AD1 (io), 39 P0.0/AD0 (io), 40 VCC (power)

## P80C51FA-5A
designator U?
80C51 8-Bit Microcontroller Family: 128 B RAM, ROMless, 2.7V-5.5V, Low Power, High Speed
footprint SOT187-2_N (Leaded Chip Carrier, 44-Leads, Body 16.6x16.6mm, Pitch 1.27mm, IPC Medium Density)
footprint SOT187-2_L (Leaded Chip Carrier, 44-Leads, Body 16.6x16.6mm, Pitch 1.27mm, IPC High Density)
footprint SOT187-2_M (Leaded Chip Carrier, 44-Leads, Body 16.6x16.6mm, Pitch 1.27mm, IPC Low Density)
pins: 1 NIC, 2 P1.0/T2 (io), 3 P1.1/T2EX (io), 4 P1.2/ECI (io), 5 P1.3/CEX0 (io), 6 P1.4/CEX1 (io), 7 P1.5/CEX2 (io), 8 P1.6/CEX3 (io), 9 P1.7/CEX4 (io), 10 RST (in), 11 P3.0/RxD (io), 12 NIC, 13 P3.1/TxD (io), 14 P3.2/~{INT}0 (io), 15 P3.3/~{INT}1 (io), 16 P3.4/T0 (io), 17 P3.5/T1 (io), 18 P3.6/~{WR} (io), 19 P3.7/~{RD} (io), 20 XTAL2 (out), 21 XTAL1 (in), 22 VSS (power), 23 NIC, 24 P2.0/A8 (io), 25 P2.1/A9 (io), 26 P2.2/A10 (io), 27 P2.3/A11 (io), 28 P2.4/A12 (io), 29 P2.5/A13 (io), 30 P2.6/A14 (io), 31 P2.7/A15 (io), 32 ~{PSEN} (out), 33 ALE/~{PROG} (io), 34 NIC, 35 ~{EA}/VPP (in), 36 P0.7/AD7 (io), 37 P0.6/AD6 (io), 38 P0.5/AD5 (io), 39 P0.4/AD4 (io), 40 P0.3/AD3 (io), 41 P0.2/AD2 (io), 42 P0.1/AD1 (io), 43 P0.0/AD0 (io), 44 VCC (power)

## P80C51FA-5B
designator U?
80C51 8-Bit Microcontroller Family: 128 B RAM, ROMless, 2.7V-5.5V, Low Power, High Speed
footprint SOT307-2_N (QFP, 44-Leads, Body 10x10mm, Pitch 0.8mm, IPC Medium Density)
footprint SOT307-2_L (QFP, 44-Leads, Body 10x10mm, Pitch 0.8mm, IPC High Density)
footprint SOT307-2_M (QFP, 44-Leads, Body 10x10mm, Pitch 0.8mm, IPC Low Density)
pins: 1 P1.5/CEX2 (io), 2 P1.6/CEX3 (io), 3 P1.7/CEX4 (io), 4 RST (in), 5 P3.0/RxD (io), 6 NIC, 7 P3.1/TxD (io), 8 P3.2/~{INT}0 (io), 9 P3.3/~{INT}1 (io), 10 P3.4/T0 (io), 11 P3.5/T1 (io), 12 P3.6/~{WR} (io), 13 P3.7/~{RD} (io), 14 XTAL2 (out), 15 XTAL1 (in), 16 VSS (power), 17 NIC, 18 P2.0/A8 (io), 19 P2.1/A9 (io), 20 P2.2/A10 (io), 21 P2.3/A11 (io), 22 P2.4/A12 (io), 23 P2.5/A13 (io), 24 P2.6/A14 (io), 25 P2.7/A15 (io), 26 ~{PSEN} (out), 27 ALE/~{PROG} (io), 28 NIC, 29 ~{EA}/VPP (in), 30 P0.7/AD7 (io), 31 P0.6/AD6 (io), 32 P0.5/AD5 (io), 33 P0.4/AD4 (io), 34 P0.3/AD3 (io), 35 P0.2/AD2 (io), 36 P0.1/AD1 (io), 37 P0.0/AD0 (io), 38 VCC (power), 39 NIC, 40 P1.0/T2 (io), 41 P1.1/T2EX (io), 42 P1.2/ECI (io), 43 P1.3/CEX0 (io), 44 P1.4/CEX1 (io)

## P80C51FA-5N
designator U?
80C51 8-Bit Microcontroller Family: 128 B RAM, ROMless, 2.7V-5.5V, Low Power, High Speed
footprint SOT129-1 (DIP, Plastic; 40 Leads; Row Spacing 15.24 mm; Pitch 2.54 mm)
pins: 1 P1.0/T2 (io), 2 P1.1/T2EX (io), 3 P1.2/ECI (io), 4 P1.3/CEX0 (io), 5 P1.4/CEX1 (io), 6 P1.5/CEX2 (io), 7 P1.6/CEX3 (io), 8 P1.7/CEX4 (io), 9 RST (in), 10 P3.0/RxD (io), 11 P3.1/TxD (io), 12 P3.2/~{INT}0 (io), 13 P3.3/~{INT}1 (io), 14 P3.4/T0 (io), 15 P3.5/T1 (io), 16 P3.6/~{WR} (io), 17 P3.7/~{RD} (io), 18 XTAL2 (out), 19 XTAL1 (in), 20 VSS (power), 21 P2.0/A8 (io), 22 P2.1/A9 (io), 23 P2.2/A10 (io), 24 P2.3/A11 (io), 25 P2.4/A12 (io), 26 P2.5/A13 (io), 27 P2.6/A14 (io), 28 P2.7/A15 (io), 29 ~{PSEN} (out), 30 ALE/~{PROG} (io), 31 ~{EA}/VPP (in), 32 P0.7/AD7 (io), 33 P0.6/AD6 (io), 34 P0.5/AD5 (io), 35 P0.4/AD4 (io), 36 P0.3/AD3 (io), 37 P0.2/AD2 (io), 38 P0.1/AD1 (io), 39 P0.0/AD0 (io), 40 VCC (power)

## P80C51FA-IA
designator U?
80C51 8-Bit Microcontroller Family: 128 B RAM, ROMless, 5V, Low Power, High Speed
footprint SOT187-2_N (Leaded Chip Carrier, 44-Leads, Body 16.6x16.6mm, Pitch 1.27mm, IPC Medium Density)
footprint SOT187-2_L (Leaded Chip Carrier, 44-Leads, Body 16.6x16.6mm, Pitch 1.27mm, IPC High Density)
footprint SOT187-2_M (Leaded Chip Carrier, 44-Leads, Body 16.6x16.6mm, Pitch 1.27mm, IPC Low Density)
pins: 1 NIC, 2 P1.0/T2 (io), 3 P1.1/T2EX (io), 4 P1.2/ECI (io), 5 P1.3/CEX0 (io), 6 P1.4/CEX1 (io), 7 P1.5/CEX2 (io), 8 P1.6/CEX3 (io), 9 P1.7/CEX4 (io), 10 RST (in), 11 P3.0/RxD (io), 12 NIC, 13 P3.1/TxD (io), 14 P3.2/~{INT}0 (io), 15 P3.3/~{INT}1 (io), 16 P3.4/T0 (io), 17 P3.5/T1 (io), 18 P3.6/~{WR} (io), 19 P3.7/~{RD} (io), 20 XTAL2 (out), 21 XTAL1 (in), 22 VSS (power), 23 NIC, 24 P2.0/A8 (io), 25 P2.1/A9 (io), 26 P2.2/A10 (io), 27 P2.3/A11 (io), 28 P2.4/A12 (io), 29 P2.5/A13 (io), 30 P2.6/A14 (io), 31 P2.7/A15 (io), 32 ~{PSEN} (out), 33 ALE/~{PROG} (io), 34 NIC, 35 ~{EA}/VPP (in), 36 P0.7/AD7 (io), 37 P0.6/AD6 (io), 38 P0.5/AD5 (io), 39 P0.4/AD4 (io), 40 P0.3/AD3 (io), 41 P0.2/AD2 (io), 42 P0.1/AD1 (io), 43 P0.0/AD0 (io), 44 VCC (power)

## P80C51FA-IB
designator U?
80C51 8-Bit Microcontroller Family: 128 B RAM, ROMless, 5V, Low Power, High Speed
footprint SOT307-2_N (QFP, 44-Leads, Body 10x10mm, Pitch 0.8mm, IPC Medium Density)
footprint SOT307-2_L (QFP, 44-Leads, Body 10x10mm, Pitch 0.8mm, IPC High Density)
footprint SOT307-2_M (QFP, 44-Leads, Body 10x10mm, Pitch 0.8mm, IPC Low Density)
pins: 1 P1.5/CEX2 (io), 2 P1.6/CEX3 (io), 3 P1.7/CEX4 (io), 4 RST (in), 5 P3.0/RxD (io), 6 NIC, 7 P3.1/TxD (io), 8 P3.2/~{INT}0 (io), 9 P3.3/~{INT}1 (io), 10 P3.4/T0 (io), 11 P3.5/T1 (io), 12 P3.6/~{WR} (io), 13 P3.7/~{RD} (io), 14 XTAL2 (out), 15 XTAL1 (in), 16 VSS (power), 17 NIC, 18 P2.0/A8 (io), 19 P2.1/A9 (io), 20 P2.2/A10 (io), 21 P2.3/A11 (io), 22 P2.4/A12 (io), 23 P2.5/A13 (io), 24 P2.6/A14 (io), 25 P2.7/A15 (io), 26 ~{PSEN} (out), 27 ALE/~{PROG} (io), 28 NIC, 29 ~{EA}/VPP (in), 30 P0.7/AD7 (io), 31 P0.6/AD6 (io), 32 P0.5/AD5 (io), 33 P0.4/AD4 (io), 34 P0.3/AD3 (io), 35 P0.2/AD2 (io), 36 P0.1/AD1 (io), 37 P0.0/AD0 (io), 38 VCC (power), 39 NIC, 40 P1.0/T2 (io), 41 P1.1/T2EX (io), 42 P1.2/ECI (io), 43 P1.3/CEX0 (io), 44 P1.4/CEX1 (io)

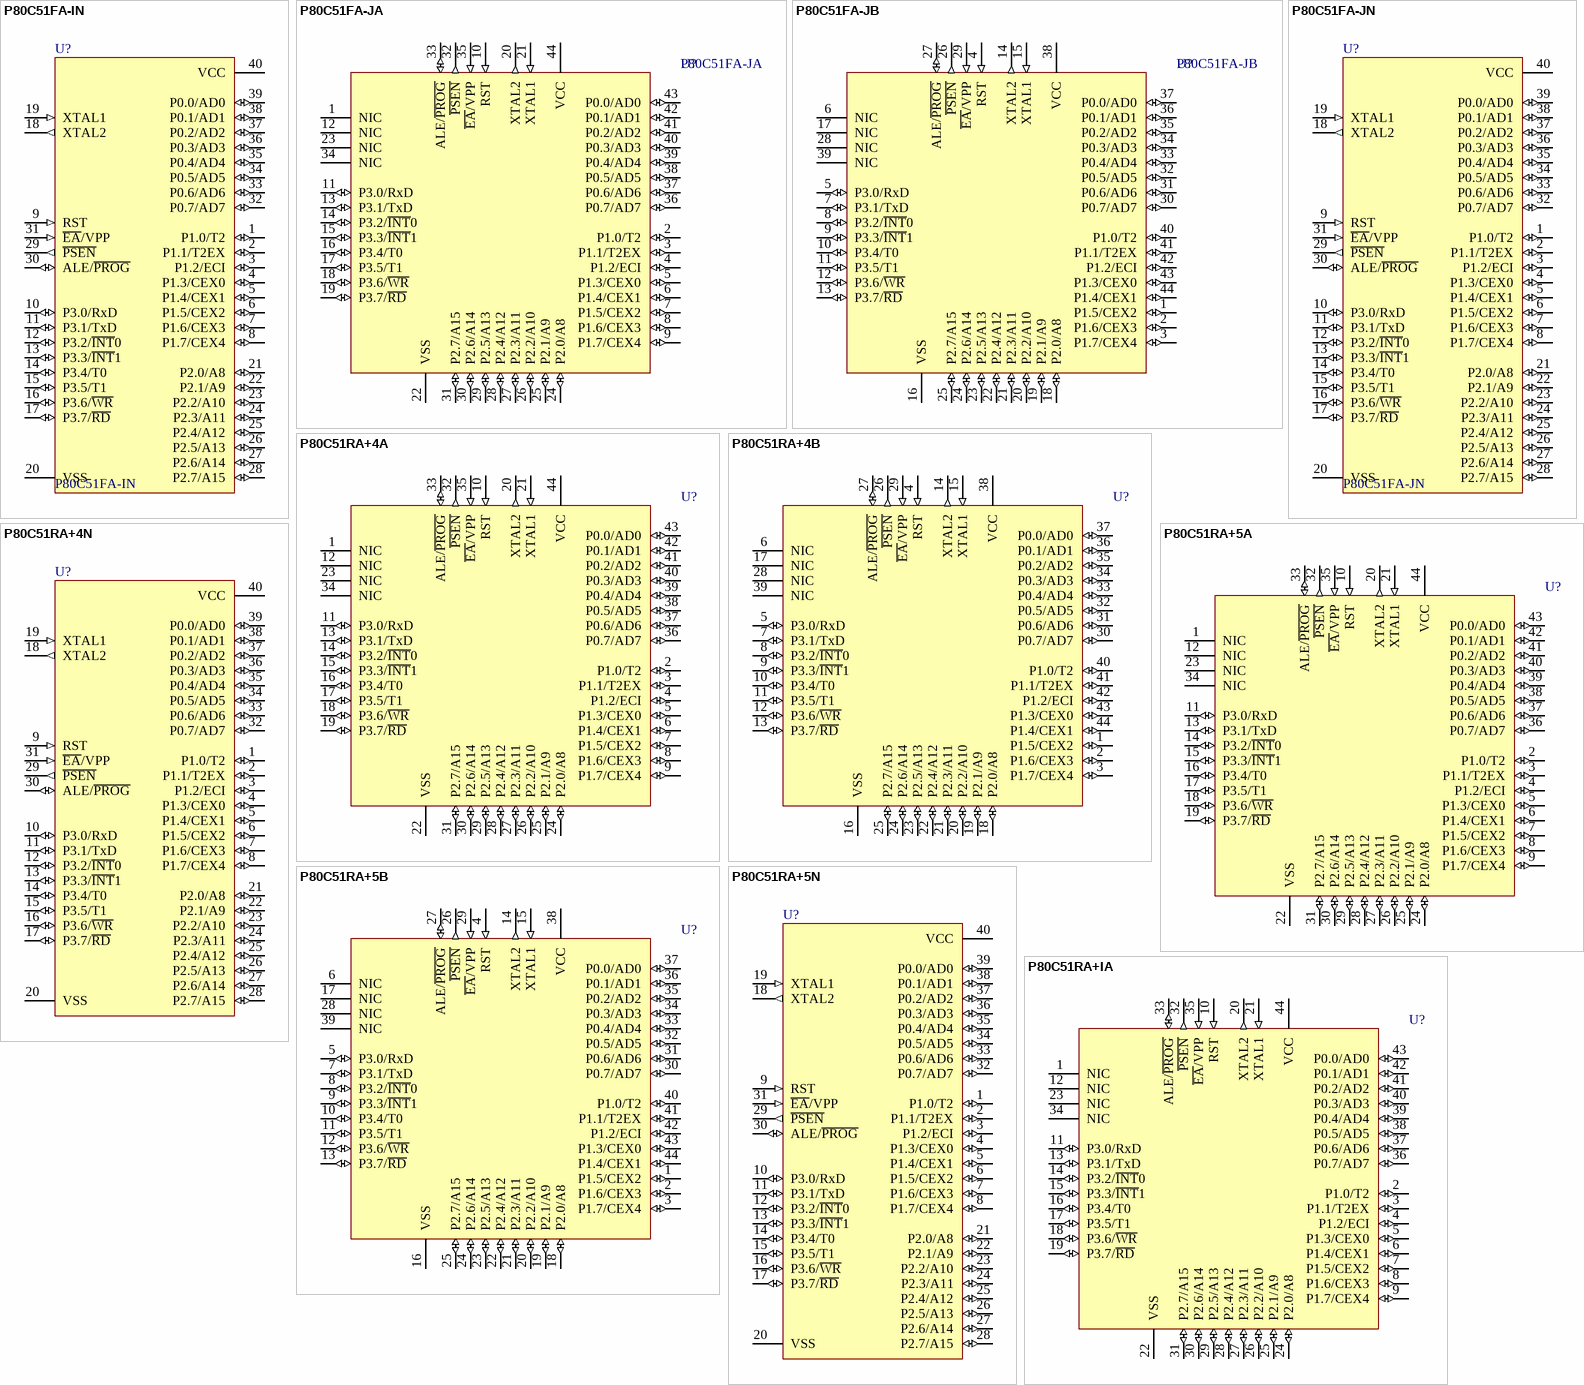
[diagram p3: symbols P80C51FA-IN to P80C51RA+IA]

## P80C51FA-IN
designator U?
80C51 8-Bit Microcontroller Family: 128 B RAM, ROMless, 5V, Low Power, High Speed
footprint SOT129-1 (DIP, Plastic; 40 Leads; Row Spacing 15.24 mm; Pitch 2.54 mm)
pins: 1 P1.0/T2 (io), 2 P1.1/T2EX (io), 3 P1.2/ECI (io), 4 P1.3/CEX0 (io), 5 P1.4/CEX1 (io), 6 P1.5/CEX2 (io), 7 P1.6/CEX3 (io), 8 P1.7/CEX4 (io), 9 RST (in), 10 P3.0/RxD (io), 11 P3.1/TxD (io), 12 P3.2/~{INT}0 (io), 13 P3.3/~{INT}1 (io), 14 P3.4/T0 (io), 15 P3.5/T1 (io), 16 P3.6/~{WR} (io), 17 P3.7/~{RD} (io), 18 XTAL2 (out), 19 XTAL1 (in), 20 VSS (power), 21 P2.0/A8 (io), 22 P2.1/A9 (io), 23 P2.2/A10 (io), 24 P2.3/A11 (io), 25 P2.4/A12 (io), 26 P2.5/A13 (io), 27 P2.6/A14 (io), 28 P2.7/A15 (io), 29 ~{PSEN} (out), 30 ALE/~{PROG} (io), 31 ~{EA}/VPP (in), 32 P0.7/AD7 (io), 33 P0.6/AD6 (io), 34 P0.5/AD5 (io), 35 P0.4/AD4 (io), 36 P0.3/AD3 (io), 37 P0.2/AD2 (io), 38 P0.1/AD1 (io), 39 P0.0/AD0 (io), 40 VCC (power)

## P80C51FA-JA
designator U?
80C51 8-Bit Microcontroller Family: 128 B RAM, ROMless, 5V, Low Power, High Speed
footprint SOT187-2_N (Leaded Chip Carrier, 44-Leads, Body 16.6x16.6mm, Pitch 1.27mm, IPC Medium Density)
footprint SOT187-2_L (Leaded Chip Carrier, 44-Leads, Body 16.6x16.6mm, Pitch 1.27mm, IPC High Density)
footprint SOT187-2_M (Leaded Chip Carrier, 44-Leads, Body 16.6x16.6mm, Pitch 1.27mm, IPC Low Density)
pins: 1 NIC, 2 P1.0/T2 (io), 3 P1.1/T2EX (io), 4 P1.2/ECI (io), 5 P1.3/CEX0 (io), 6 P1.4/CEX1 (io), 7 P1.5/CEX2 (io), 8 P1.6/CEX3 (io), 9 P1.7/CEX4 (io), 10 RST (in), 11 P3.0/RxD (io), 12 NIC, 13 P3.1/TxD (io), 14 P3.2/~{INT}0 (io), 15 P3.3/~{INT}1 (io), 16 P3.4/T0 (io), 17 P3.5/T1 (io), 18 P3.6/~{WR} (io), 19 P3.7/~{RD} (io), 20 XTAL2 (out), 21 XTAL1 (in), 22 VSS (power), 23 NIC, 24 P2.0/A8 (io), 25 P2.1/A9 (io), 26 P2.2/A10 (io), 27 P2.3/A11 (io), 28 P2.4/A12 (io), 29 P2.5/A13 (io), 30 P2.6/A14 (io), 31 P2.7/A15 (io), 32 ~{PSEN} (out), 33 ALE/~{PROG} (io), 34 NIC, 35 ~{EA}/VPP (in), 36 P0.7/AD7 (io), 37 P0.6/AD6 (io), 38 P0.5/AD5 (io), 39 P0.4/AD4 (io), 40 P0.3/AD3 (io), 41 P0.2/AD2 (io), 42 P0.1/AD1 (io), 43 P0.0/AD0 (io), 44 VCC (power)

## P80C51FA-JB
designator U?
80C51 8-Bit Microcontroller Family: 128 B RAM, ROMless, 5V, Low Power, High Speed
footprint SOT307-2_N (QFP, 44-Leads, Body 10x10mm, Pitch 0.8mm, IPC Medium Density)
footprint SOT307-2_L (QFP, 44-Leads, Body 10x10mm, Pitch 0.8mm, IPC High Density)
footprint SOT307-2_M (QFP, 44-Leads, Body 10x10mm, Pitch 0.8mm, IPC Low Density)
pins: 1 P1.5/CEX2 (io), 2 P1.6/CEX3 (io), 3 P1.7/CEX4 (io), 4 RST (in), 5 P3.0/RxD (io), 6 NIC, 7 P3.1/TxD (io), 8 P3.2/~{INT}0 (io), 9 P3.3/~{INT}1 (io), 10 P3.4/T0 (io), 11 P3.5/T1 (io), 12 P3.6/~{WR} (io), 13 P3.7/~{RD} (io), 14 XTAL2 (out), 15 XTAL1 (in), 16 VSS (power), 17 NIC, 18 P2.0/A8 (io), 19 P2.1/A9 (io), 20 P2.2/A10 (io), 21 P2.3/A11 (io), 22 P2.4/A12 (io), 23 P2.5/A13 (io), 24 P2.6/A14 (io), 25 P2.7/A15 (io), 26 ~{PSEN} (out), 27 ALE/~{PROG} (io), 28 NIC, 29 ~{EA}/VPP (in), 30 P0.7/AD7 (io), 31 P0.6/AD6 (io), 32 P0.5/AD5 (io), 33 P0.4/AD4 (io), 34 P0.3/AD3 (io), 35 P0.2/AD2 (io), 36 P0.1/AD1 (io), 37 P0.0/AD0 (io), 38 VCC (power), 39 NIC, 40 P1.0/T2 (io), 41 P1.1/T2EX (io), 42 P1.2/ECI (io), 43 P1.3/CEX0 (io), 44 P1.4/CEX1 (io)

## P80C51FA-JN
designator U?
80C51 8-Bit Microcontroller Family: 128 B RAM, ROMless, 5V, Low Power, High Speed
footprint SOT129-1 (DIP, Plastic; 40 Leads; Row Spacing 15.24 mm; Pitch 2.54 mm)
pins: 1 P1.0/T2 (io), 2 P1.1/T2EX (io), 3 P1.2/ECI (io), 4 P1.3/CEX0 (io), 5 P1.4/CEX1 (io), 6 P1.5/CEX2 (io), 7 P1.6/CEX3 (io), 8 P1.7/CEX4 (io), 9 RST (in), 10 P3.0/RxD (io), 11 P3.1/TxD (io), 12 P3.2/~{INT}0 (io), 13 P3.3/~{INT}1 (io), 14 P3.4/T0 (io), 15 P3.5/T1 (io), 16 P3.6/~{WR} (io), 17 P3.7/~{RD} (io), 18 XTAL2 (out), 19 XTAL1 (in), 20 VSS (power), 21 P2.0/A8 (io), 22 P2.1/A9 (io), 23 P2.2/A10 (io), 24 P2.3/A11 (io), 25 P2.4/A12 (io), 26 P2.5/A13 (io), 27 P2.6/A14 (io), 28 P2.7/A15 (io), 29 ~{PSEN} (out), 30 ALE/~{PROG} (io), 31 ~{EA}/VPP (in), 32 P0.7/AD7 (io), 33 P0.6/AD6 (io), 34 P0.5/AD5 (io), 35 P0.4/AD4 (io), 36 P0.3/AD3 (io), 37 P0.2/AD2 (io), 38 P0.1/AD1 (io), 39 P0.0/AD0 (io), 40 VCC (power)

## P80C51RA+4A
designator U?
80C51 8-Bit Microcontroller Family: 512 B RAM, ROMless, 2.7V-5.5V, Low Power, High Speed
footprint SOT187-2_N (Leaded Chip Carrier, 44-Leads, Body 16.6x16.6mm, Pitch 1.27mm, IPC Medium Density)
footprint SOT187-2_L (Leaded Chip Carrier, 44-Leads, Body 16.6x16.6mm, Pitch 1.27mm, IPC High Density)
footprint SOT187-2_M (Leaded Chip Carrier, 44-Leads, Body 16.6x16.6mm, Pitch 1.27mm, IPC Low Density)
pins: 1 NIC, 2 P1.0/T2 (io), 3 P1.1/T2EX (io), 4 P1.2/ECI (io), 5 P1.3/CEX0 (io), 6 P1.4/CEX1 (io), 7 P1.5/CEX2 (io), 8 P1.6/CEX3 (io), 9 P1.7/CEX4 (io), 10 RST (in), 11 P3.0/RxD (io), 12 NIC, 13 P3.1/TxD (io), 14 P3.2/~{INT}0 (io), 15 P3.3/~{INT}1 (io), 16 P3.4/T0 (io), 17 P3.5/T1 (io), 18 P3.6/~{WR} (io), 19 P3.7/~{RD} (io), 20 XTAL2 (out), 21 XTAL1 (in), 22 VSS (power), 23 NIC, 24 P2.0/A8 (io), 25 P2.1/A9 (io), 26 P2.2/A10 (io), 27 P2.3/A11 (io), 28 P2.4/A12 (io), 29 P2.5/A13 (io), 30 P2.6/A14 (io), 31 P2.7/A15 (io), 32 ~{PSEN} (out), 33 ALE/~{PROG} (io), 34 NIC, 35 ~{EA}/VPP (in), 36 P0.7/AD7 (io), 37 P0.6/AD6 (io), 38 P0.5/AD5 (io), 39 P0.4/AD4 (io), 40 P0.3/AD3 (io), 41 P0.2/AD2 (io), 42 P0.1/AD1 (io), 43 P0.0/AD0 (io), 44 VCC (power)

## P80C51RA+4B
designator U?
80C51 8-Bit Microcontroller Family: 512 B RAM, ROMless, 2.7V-5.5V, Low Power, High Speed
footprint SOT307-2_N (QFP, 44-Leads, Body 10x10mm, Pitch 0.8mm, IPC Medium Density)
footprint SOT307-2_L (QFP, 44-Leads, Body 10x10mm, Pitch 0.8mm, IPC High Density)
footprint SOT307-2_M (QFP, 44-Leads, Body 10x10mm, Pitch 0.8mm, IPC Low Density)
pins: 1 P1.5/CEX2 (io), 2 P1.6/CEX3 (io), 3 P1.7/CEX4 (io), 4 RST (in), 5 P3.0/RxD (io), 6 NIC, 7 P3.1/TxD (io), 8 P3.2/~{INT}0 (io), 9 P3.3/~{INT}1 (io), 10 P3.4/T0 (io), 11 P3.5/T1 (io), 12 P3.6/~{WR} (io), 13 P3.7/~{RD} (io), 14 XTAL2 (out), 15 XTAL1 (in), 16 VSS (power), 17 NIC, 18 P2.0/A8 (io), 19 P2.1/A9 (io), 20 P2.2/A10 (io), 21 P2.3/A11 (io), 22 P2.4/A12 (io), 23 P2.5/A13 (io), 24 P2.6/A14 (io), 25 P2.7/A15 (io), 26 ~{PSEN} (out), 27 ALE/~{PROG} (io), 28 NIC, 29 ~{EA}/VPP (in), 30 P0.7/AD7 (io), 31 P0.6/AD6 (io), 32 P0.5/AD5 (io), 33 P0.4/AD4 (io), 34 P0.3/AD3 (io), 35 P0.2/AD2 (io), 36 P0.1/AD1 (io), 37 P0.0/AD0 (io), 38 VCC (power), 39 NIC, 40 P1.0/T2 (io), 41 P1.1/T2EX (io), 42 P1.2/ECI (io), 43 P1.3/CEX0 (io), 44 P1.4/CEX1 (io)

## P80C51RA+4N
designator U?
80C51 8-Bit Microcontroller Family: 512 B RAM, ROMless, 2.7V-5.5V, Low Power, High Speed
footprint SOT129-1 (DIP, Plastic; 40 Leads; Row Spacing 15.24 mm; Pitch 2.54 mm)
pins: 1 P1.0/T2 (io), 2 P1.1/T2EX (io), 3 P1.2/ECI (io), 4 P1.3/CEX0 (io), 5 P1.4/CEX1 (io), 6 P1.5/CEX2 (io), 7 P1.6/CEX3 (io), 8 P1.7/CEX4 (io), 9 RST (in), 10 P3.0/RxD (io), 11 P3.1/TxD (io), 12 P3.2/~{INT}0 (io), 13 P3.3/~{INT}1 (io), 14 P3.4/T0 (io), 15 P3.5/T1 (io), 16 P3.6/~{WR} (io), 17 P3.7/~{RD} (io), 18 XTAL2 (out), 19 XTAL1 (in), 20 VSS (power), 21 P2.0/A8 (io), 22 P2.1/A9 (io), 23 P2.2/A10 (io), 24 P2.3/A11 (io), 25 P2.4/A12 (io), 26 P2.5/A13 (io), 27 P2.6/A14 (io), 28 P2.7/A15 (io), 29 ~{PSEN} (out), 30 ALE/~{PROG} (io), 31 ~{EA}/VPP (in), 32 P0.7/AD7 (io), 33 P0.6/AD6 (io), 34 P0.5/AD5 (io), 35 P0.4/AD4 (io), 36 P0.3/AD3 (io), 37 P0.2/AD2 (io), 38 P0.1/AD1 (io), 39 P0.0/AD0 (io), 40 VCC (power)

## P80C51RA+5A
designator U?
80C51 8-Bit Microcontroller Family: 512 B RAM, ROMless, 2.7V-5.5V, Low Power, High Speed
footprint SOT187-2_N (Leaded Chip Carrier, 44-Leads, Body 16.6x16.6mm, Pitch 1.27mm, IPC Medium Density)
footprint SOT187-2_L (Leaded Chip Carrier, 44-Leads, Body 16.6x16.6mm, Pitch 1.27mm, IPC High Density)
footprint SOT187-2_M (Leaded Chip Carrier, 44-Leads, Body 16.6x16.6mm, Pitch 1.27mm, IPC Low Density)
pins: 1 NIC, 2 P1.0/T2 (io), 3 P1.1/T2EX (io), 4 P1.2/ECI (io), 5 P1.3/CEX0 (io), 6 P1.4/CEX1 (io), 7 P1.5/CEX2 (io), 8 P1.6/CEX3 (io), 9 P1.7/CEX4 (io), 10 RST (in), 11 P3.0/RxD (io), 12 NIC, 13 P3.1/TxD (io), 14 P3.2/~{INT}0 (io), 15 P3.3/~{INT}1 (io), 16 P3.4/T0 (io), 17 P3.5/T1 (io), 18 P3.6/~{WR} (io), 19 P3.7/~{RD} (io), 20 XTAL2 (out), 21 XTAL1 (in), 22 VSS (power), 23 NIC, 24 P2.0/A8 (io), 25 P2.1/A9 (io), 26 P2.2/A10 (io), 27 P2.3/A11 (io), 28 P2.4/A12 (io), 29 P2.5/A13 (io), 30 P2.6/A14 (io), 31 P2.7/A15 (io), 32 ~{PSEN} (out), 33 ALE/~{PROG} (io), 34 NIC, 35 ~{EA}/VPP (in), 36 P0.7/AD7 (io), 37 P0.6/AD6 (io), 38 P0.5/AD5 (io), 39 P0.4/AD4 (io), 40 P0.3/AD3 (io), 41 P0.2/AD2 (io), 42 P0.1/AD1 (io), 43 P0.0/AD0 (io), 44 VCC (power)

## P80C51RA+5B
designator U?
80C51 8-Bit Microcontroller Family: 512 B RAM, ROMless, 2.7V-5.5V, Low Power, High Speed
footprint SOT307-2_N (QFP, 44-Leads, Body 10x10mm, Pitch 0.8mm, IPC Medium Density)
footprint SOT307-2_L (QFP, 44-Leads, Body 10x10mm, Pitch 0.8mm, IPC High Density)
footprint SOT307-2_M (QFP, 44-Leads, Body 10x10mm, Pitch 0.8mm, IPC Low Density)
pins: 1 P1.5/CEX2 (io), 2 P1.6/CEX3 (io), 3 P1.7/CEX4 (io), 4 RST (in), 5 P3.0/RxD (io), 6 NIC, 7 P3.1/TxD (io), 8 P3.2/~{INT}0 (io), 9 P3.3/~{INT}1 (io), 10 P3.4/T0 (io), 11 P3.5/T1 (io), 12 P3.6/~{WR} (io), 13 P3.7/~{RD} (io), 14 XTAL2 (out), 15 XTAL1 (in), 16 VSS (power), 17 NIC, 18 P2.0/A8 (io), 19 P2.1/A9 (io), 20 P2.2/A10 (io), 21 P2.3/A11 (io), 22 P2.4/A12 (io), 23 P2.5/A13 (io), 24 P2.6/A14 (io), 25 P2.7/A15 (io), 26 ~{PSEN} (out), 27 ALE/~{PROG} (io), 28 NIC, 29 ~{EA}/VPP (in), 30 P0.7/AD7 (io), 31 P0.6/AD6 (io), 32 P0.5/AD5 (io), 33 P0.4/AD4 (io), 34 P0.3/AD3 (io), 35 P0.2/AD2 (io), 36 P0.1/AD1 (io), 37 P0.0/AD0 (io), 38 VCC (power), 39 NIC, 40 P1.0/T2 (io), 41 P1.1/T2EX (io), 42 P1.2/ECI (io), 43 P1.3/CEX0 (io), 44 P1.4/CEX1 (io)

## P80C51RA+5N
designator U?
80C51 8-Bit Microcontroller Family: 512 B RAM, ROMless, 2.7V-5.5V, Low Power, High Speed
footprint SOT129-1 (DIP, Plastic; 40 Leads; Row Spacing 15.24 mm; Pitch 2.54 mm)
pins: 1 P1.0/T2 (io), 2 P1.1/T2EX (io), 3 P1.2/ECI (io), 4 P1.3/CEX0 (io), 5 P1.4/CEX1 (io), 6 P1.5/CEX2 (io), 7 P1.6/CEX3 (io), 8 P1.7/CEX4 (io), 9 RST (in), 10 P3.0/RxD (io), 11 P3.1/TxD (io), 12 P3.2/~{INT}0 (io), 13 P3.3/~{INT}1 (io), 14 P3.4/T0 (io), 15 P3.5/T1 (io), 16 P3.6/~{WR} (io), 17 P3.7/~{RD} (io), 18 XTAL2 (out), 19 XTAL1 (in), 20 VSS (power), 21 P2.0/A8 (io), 22 P2.1/A9 (io), 23 P2.2/A10 (io), 24 P2.3/A11 (io), 25 P2.4/A12 (io), 26 P2.5/A13 (io), 27 P2.6/A14 (io), 28 P2.7/A15 (io), 29 ~{PSEN} (out), 30 ALE/~{PROG} (io), 31 ~{EA}/VPP (in), 32 P0.7/AD7 (io), 33 P0.6/AD6 (io), 34 P0.5/AD5 (io), 35 P0.4/AD4 (io), 36 P0.3/AD3 (io), 37 P0.2/AD2 (io), 38 P0.1/AD1 (io), 39 P0.0/AD0 (io), 40 VCC (power)

## P80C51RA+IA
designator U?
80C51 8-Bit Microcontroller Family: 512 B RAM, ROMless, 5V, Low Power, High Speed
footprint SOT187-2_N (Leaded Chip Carrier, 44-Leads, Body 16.6x16.6mm, Pitch 1.27mm, IPC Medium Density)
footprint SOT187-2_L (Leaded Chip Carrier, 44-Leads, Body 16.6x16.6mm, Pitch 1.27mm, IPC High Density)
footprint SOT187-2_M (Leaded Chip Carrier, 44-Leads, Body 16.6x16.6mm, Pitch 1.27mm, IPC Low Density)
pins: 1 NIC, 2 P1.0/T2 (io), 3 P1.1/T2EX (io), 4 P1.2/ECI (io), 5 P1.3/CEX0 (io), 6 P1.4/CEX1 (io), 7 P1.5/CEX2 (io), 8 P1.6/CEX3 (io), 9 P1.7/CEX4 (io), 10 RST (in), 11 P3.0/RxD (io), 12 NIC, 13 P3.1/TxD (io), 14 P3.2/~{INT}0 (io), 15 P3.3/~{INT}1 (io), 16 P3.4/T0 (io), 17 P3.5/T1 (io), 18 P3.6/~{WR} (io), 19 P3.7/~{RD} (io), 20 XTAL2 (out), 21 XTAL1 (in), 22 VSS (power), 23 NIC, 24 P2.0/A8 (io), 25 P2.1/A9 (io), 26 P2.2/A10 (io), 27 P2.3/A11 (io), 28 P2.4/A12 (io), 29 P2.5/A13 (io), 30 P2.6/A14 (io), 31 P2.7/A15 (io), 32 ~{PSEN} (out), 33 ALE/~{PROG} (io), 34 NIC, 35 ~{EA}/VPP (in), 36 P0.7/AD7 (io), 37 P0.6/AD6 (io), 38 P0.5/AD5 (io), 39 P0.4/AD4 (io), 40 P0.3/AD3 (io), 41 P0.2/AD2 (io), 42 P0.1/AD1 (io), 43 P0.0/AD0 (io), 44 VCC (power)

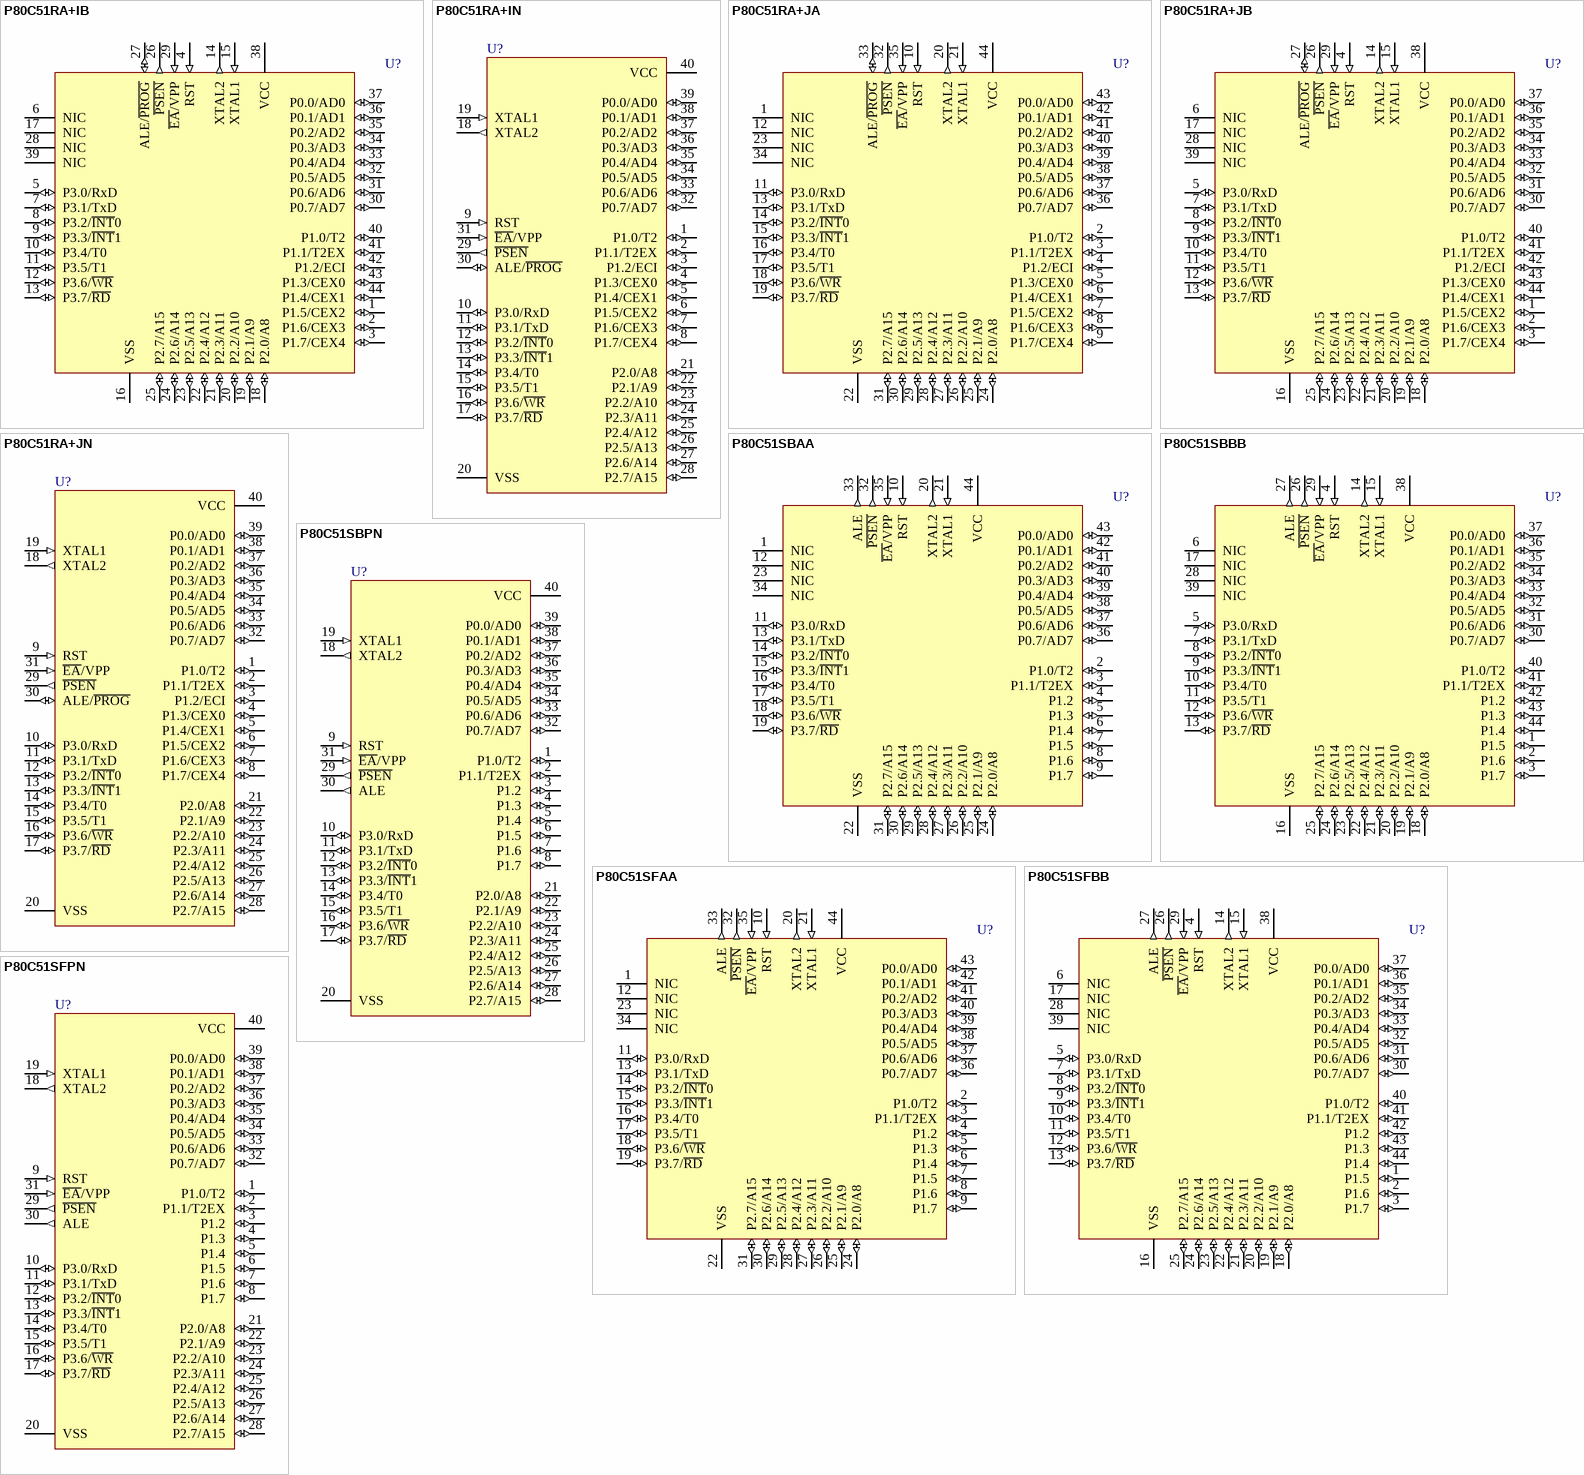
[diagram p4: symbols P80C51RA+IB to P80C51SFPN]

## P80C51RA+IB
designator U?
80C51 8-Bit Microcontroller Family: 512 B RAM, ROMless, 5V, Low Power, High Speed
footprint SOT307-2_N (QFP, 44-Leads, Body 10x10mm, Pitch 0.8mm, IPC Medium Density)
footprint SOT307-2_L (QFP, 44-Leads, Body 10x10mm, Pitch 0.8mm, IPC High Density)
footprint SOT307-2_M (QFP, 44-Leads, Body 10x10mm, Pitch 0.8mm, IPC Low Density)
pins: 1 P1.5/CEX2 (io), 2 P1.6/CEX3 (io), 3 P1.7/CEX4 (io), 4 RST (in), 5 P3.0/RxD (io), 6 NIC, 7 P3.1/TxD (io), 8 P3.2/~{INT}0 (io), 9 P3.3/~{INT}1 (io), 10 P3.4/T0 (io), 11 P3.5/T1 (io), 12 P3.6/~{WR} (io), 13 P3.7/~{RD} (io), 14 XTAL2 (out), 15 XTAL1 (in), 16 VSS (power), 17 NIC, 18 P2.0/A8 (io), 19 P2.1/A9 (io), 20 P2.2/A10 (io), 21 P2.3/A11 (io), 22 P2.4/A12 (io), 23 P2.5/A13 (io), 24 P2.6/A14 (io), 25 P2.7/A15 (io), 26 ~{PSEN} (out), 27 ALE/~{PROG} (io), 28 NIC, 29 ~{EA}/VPP (in), 30 P0.7/AD7 (io), 31 P0.6/AD6 (io), 32 P0.5/AD5 (io), 33 P0.4/AD4 (io), 34 P0.3/AD3 (io), 35 P0.2/AD2 (io), 36 P0.1/AD1 (io), 37 P0.0/AD0 (io), 38 VCC (power), 39 NIC, 40 P1.0/T2 (io), 41 P1.1/T2EX (io), 42 P1.2/ECI (io), 43 P1.3/CEX0 (io), 44 P1.4/CEX1 (io)

## P80C51RA+IN
designator U?
80C51 8-Bit Microcontroller Family: 512 B RAM, ROMless, 5V, Low Power, High Speed
footprint SOT129-1 (DIP, Plastic; 40 Leads; Row Spacing 15.24 mm; Pitch 2.54 mm)
pins: 1 P1.0/T2 (io), 2 P1.1/T2EX (io), 3 P1.2/ECI (io), 4 P1.3/CEX0 (io), 5 P1.4/CEX1 (io), 6 P1.5/CEX2 (io), 7 P1.6/CEX3 (io), 8 P1.7/CEX4 (io), 9 RST (in), 10 P3.0/RxD (io), 11 P3.1/TxD (io), 12 P3.2/~{INT}0 (io), 13 P3.3/~{INT}1 (io), 14 P3.4/T0 (io), 15 P3.5/T1 (io), 16 P3.6/~{WR} (io), 17 P3.7/~{RD} (io), 18 XTAL2 (out), 19 XTAL1 (in), 20 VSS (power), 21 P2.0/A8 (io), 22 P2.1/A9 (io), 23 P2.2/A10 (io), 24 P2.3/A11 (io), 25 P2.4/A12 (io), 26 P2.5/A13 (io), 27 P2.6/A14 (io), 28 P2.7/A15 (io), 29 ~{PSEN} (out), 30 ALE/~{PROG} (io), 31 ~{EA}/VPP (in), 32 P0.7/AD7 (io), 33 P0.6/AD6 (io), 34 P0.5/AD5 (io), 35 P0.4/AD4 (io), 36 P0.3/AD3 (io), 37 P0.2/AD2 (io), 38 P0.1/AD1 (io), 39 P0.0/AD0 (io), 40 VCC (power)

## P80C51RA+JA
designator U?
80C51 8-Bit Microcontroller Family: 512 B RAM, ROMless, 5V, Low Power, High Speed
footprint SOT187-2_N (Leaded Chip Carrier, 44-Leads, Body 16.6x16.6mm, Pitch 1.27mm, IPC Medium Density)
footprint SOT187-2_L (Leaded Chip Carrier, 44-Leads, Body 16.6x16.6mm, Pitch 1.27mm, IPC High Density)
footprint SOT187-2_M (Leaded Chip Carrier, 44-Leads, Body 16.6x16.6mm, Pitch 1.27mm, IPC Low Density)
pins: 1 NIC, 2 P1.0/T2 (io), 3 P1.1/T2EX (io), 4 P1.2/ECI (io), 5 P1.3/CEX0 (io), 6 P1.4/CEX1 (io), 7 P1.5/CEX2 (io), 8 P1.6/CEX3 (io), 9 P1.7/CEX4 (io), 10 RST (in), 11 P3.0/RxD (io), 12 NIC, 13 P3.1/TxD (io), 14 P3.2/~{INT}0 (io), 15 P3.3/~{INT}1 (io), 16 P3.4/T0 (io), 17 P3.5/T1 (io), 18 P3.6/~{WR} (io), 19 P3.7/~{RD} (io), 20 XTAL2 (out), 21 XTAL1 (in), 22 VSS (power), 23 NIC, 24 P2.0/A8 (io), 25 P2.1/A9 (io), 26 P2.2/A10 (io), 27 P2.3/A11 (io), 28 P2.4/A12 (io), 29 P2.5/A13 (io), 30 P2.6/A14 (io), 31 P2.7/A15 (io), 32 ~{PSEN} (out), 33 ALE/~{PROG} (io), 34 NIC, 35 ~{EA}/VPP (in), 36 P0.7/AD7 (io), 37 P0.6/AD6 (io), 38 P0.5/AD5 (io), 39 P0.4/AD4 (io), 40 P0.3/AD3 (io), 41 P0.2/AD2 (io), 42 P0.1/AD1 (io), 43 P0.0/AD0 (io), 44 VCC (power)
